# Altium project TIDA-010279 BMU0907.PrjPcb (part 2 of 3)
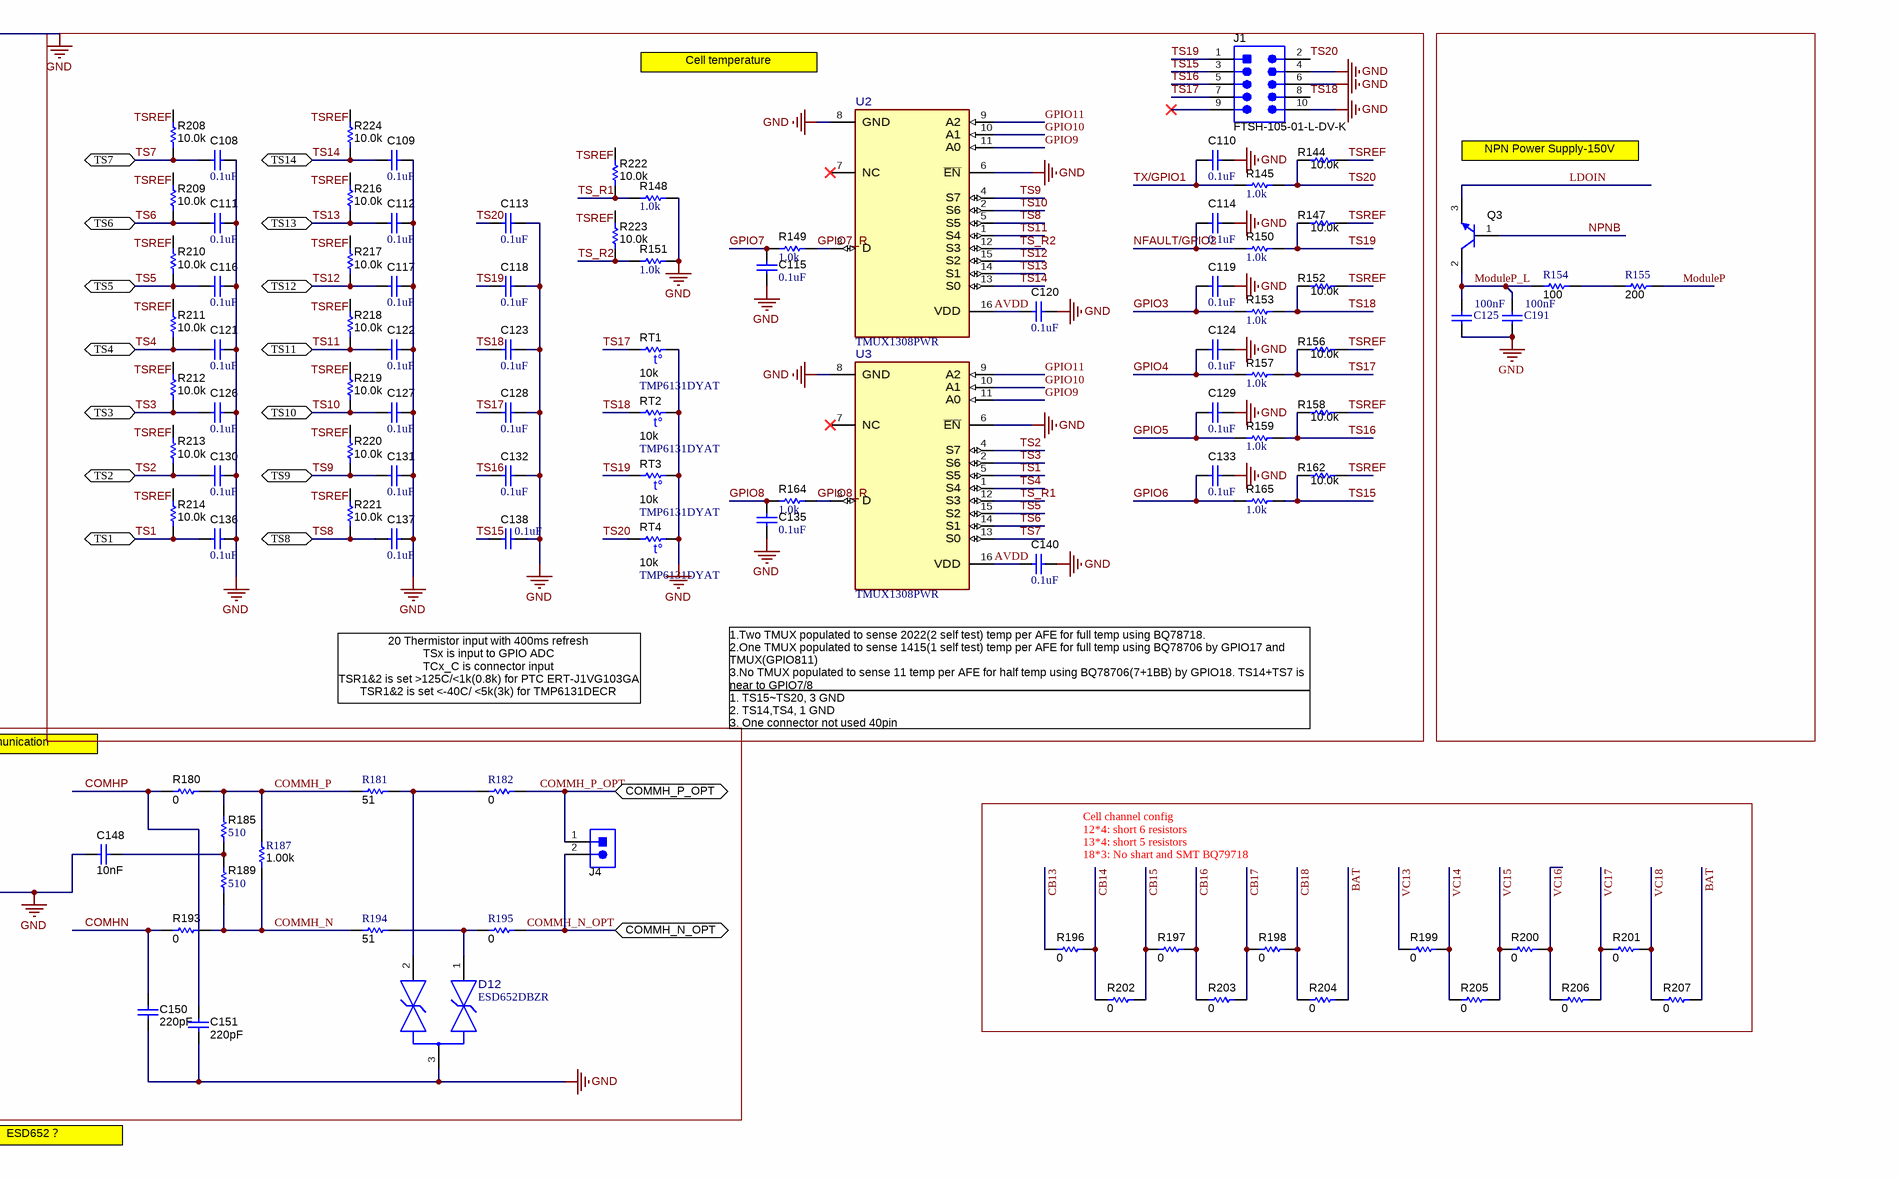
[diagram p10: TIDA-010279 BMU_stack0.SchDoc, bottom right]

## Sheet TIDA-010279 BMU_stack0.SchDoc (continued)

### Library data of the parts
C1-C4 C15-C17 C34-C36 C52-C54 C62 C68 C72-C74 C76 C80 C85 C90 C93-C95 C97 C103 C108-C124 C126-C133 C135-C138 C140 = CMP-0006356-2: CAP, CERM, 0.1 uF, 50 V, +/- 10%, X7R, AEC-Q200 Grade 1, 0402; Manufacturer: MuRata; TaMin_C: -55°C; Polarized: N; SizeAreaWB_mm2: 3; Value1: Unknown; U/M: EA; Value: 0.1uF; TaMax_C: 125°C; SizeZ_mm: 0.6; SizeX_mm: 1; SizeY_mm: 0.5; Value2: 50V; AEC Qualified: Y; Cap_F: 100nF; AEC Category: Q200
C5 C6 C8 C9 C11 C12 C19 C20 C23 C24 C27 C28 C31 C32 C39 C40 C42 C43 C47 C48 C50 C51 C56 C57 C59 C60 C65 C66 C69 C70 C77 C78 C82 C83 C86 C87 C91 C92 C99 C100 = CMP-0096840-1: Cap Ceramic 22nF 100V X7R 10% Pad SMD 0603 +125°C Automotive T/R; Manufacturer: TDK; AEC Grade: Grade 1; SizeZ_mm: 1.1mm; Tolerance_%: 0.1%; AEC Qualified: Yes; TempCo: 0.15
C7 C14 C22 C30 C37 C45 C49 C58 C61 C63 C67 C71 C75 C79 C81 C84 C88 C89 C96 C98 C101 C102 C104-C107 = CMP-0006361-2: CAP, CERM, 4700 pF, 50 V, +/- 10%, X7R, AEC-Q200 Grade 1, 0402; Manufacturer: MuRata; TaMin_C: -55°C; Polarized: N; SizeAreaWB_mm2: 3; Value1: Unknown; U/M: EA; Value: 4700pF; TaMax_C: 125°C; SizeZ_mm: 0.6; SizeX_mm: 1; SizeY_mm: 0.5; Value2: 50V; AEC Qualified: Y; Cap_F: 4.7nF; AEC Category: Q200
C18 = CMP-0080738-1: CAP, CERM, 4.7 µF, 10 V,+/- 5%, X7R, AEC-Q200 Grade 1, 0805; Manufacturer: Kemet; AEC Grade: 1; AEC Qualified: Y; SizeZ_mm: 1.45; VDC_V: 10V; SizeAreaWB_mm2: 6.75; SizeArea_mm2: 2.5; AEC Category: Q200; Value: 4.7uF; TaMax_C: 125°C; Polarized: N; TaMin_C: -55°C; SizeY_mm: 1.25; U/M: EA; SizeX_mm: 2; Cap_Case: 0805
C26 = CMP-0084773-1: CAP, CERM, 0.01 µF, 100 V,+/- 10%, X7R, AEC-Q200 Grade 1, 0603; Manufacturer: MuRata; SizeArea_mm2: 1.28; ValueDisplayed: 0.01µF; Polarized: N; AEC Grade: 1; Value2: 100V; SizeY_mm: 0.8; Cap_Case: 0603; TaMax_C: 125°C; Value: 0.01uF; SizeAreaWB_mm2: 4.68; TaMin_C: -55°C; CompType: Capacitor; AEC Category: Q200; U/M: EA; AEC Qualified: Y; SizeX_mm: 1.6
C38 C55 = CMP-0007136-5: CAP, CERM, 1 uF, 16 V, +/- 10%, X7R, AEC-Q200 Grade 1, 0603; Manufacturer: MuRata; TaMin_C: -55°C; Polarized: N; SizeAreaWB_mm2: 4.68; Value1: Unknown; U/M: EA; Value: 1uF; TaMax_C: 125°C; SizeZ_mm: 1; SizeX_mm: 1.6; SizeY_mm: 0.8; Value2: 16V; SizeArea_mm2: 1.28; AEC Qualified: Y; AEC Category: Q200
C46 C64 = CMP-0007138-4: CAP, CERM, 0.47 uF, 16 V, +/- 10%, X7R, AEC-Q200 Grade 1, 0603; Manufacturer: MuRata; Polarized: N; CompType: Capacitor; Value: 0.47uF; U/M: EA; Cap_F: 470nF; Value1: Unknown; VDC_V: 16V; TaMin_C: -55°C; TaMax_C: 125°C; AEC Category: Q200; AEC Qualified: Y; AEC Grade: 1; SizeAreaWB_mm2: 4.68; SizeX_mm: 1.6; SizeY_mm: 0.8; SizeArea_mm2: 1.28
C125 C191 = CMP-0119652-1: WCAP-CSGP Multilayer Ceramic Chip Capacitor, General Purpose, size 1206, X7R, 100nF, 100VDC; Manufacturer: Wurth Elektronik; Capacitance Tolerance: +/-10%; Case/Size Code: 1206; Dissipation Factor: 2.5%; Insulation Resistance: 1GOhm; Rated Voltage (DC): 100V; Technical Reference: X7R1206104K100DFCT10000
C147 C148 = CMP-0007143-4: CAP, CERM, 0.01 uF, 50 V, +/- 10%, X7R, AEC-Q200 Grade 1, 0603; Manufacturer: MuRata; TaMin_C: -55°C; Polarized: N; SizeAreaWB_mm2: 4.68; Value1: Unknown; U/M: EA; Value: 0.01uF; TaMax_C: 125°C; SizeZ_mm: 1; SizeX_mm: 1.6; SizeY_mm: 0.8; Value2: 50V; SizeArea_mm2: 1.28; AEC Qualified: Y; AEC Category: Q200
C149-C152 = CMP-0860329-1: CAP, CERM, 220 pF, 50 V,+/- 5%, X7R, 0603; Manufacturer: Samsung Electro-Mechanics; TaMin_C: -55°C; Polarized: N; SizeAreaWB_mm2: 4.68; U/M: EA; Value: 220pF; TaMax_C: 125°C; SizeZ_mm: 1; SizeX_mm: 1.6; SizeY_mm: 0.8; Value2: 50V; SizeArea_mm2: 1.28; CompType: Capacitor; AEC Category: Q200
D1 = CMP-0029023-2: Diode, Superfast Rectifier, 150 V, 1 A, SMA; Manufacturer: Diodes Inc.; TJmax_C: 150°C; Vr_V: 150V; Value2: 0.92V; SizeX_mm: 5.59; Green_REACh: Incomplete; SizeAreaWB_mm2: 37.3428; Value: 150V; Vf_V: 920mV; Green_Lifecycle: Not Set; Value1: 1A; SizeZ_mm: 2.87; SizeArea_mm2: 16.3228; SizeY_mm: 2.92; AEC Category: Q101; RJC_CperW: 25
D2 D3 = CMP-0002888-2: LED, Green, SMD; Manufacturer: Lite-On; Type: AlInGaP; Vf_V: 2V; Io_A: 20mA; Value1: W
D4 D5 = CMP-0033054-1: SMD16PL Series 60 V 1 A Surface Mount Schottky Rectifier - SOD-123FL; Manufacturer: Micro Commercial Co; AEC Qualified: No; SizeZ_mm: 1.35mm; TJmax_C: 125°C; Vf_V: 60V; Cap_F: 40pF; Forward Current: 1A; Max Surge Forward Current: 30A; Peak Reverse Current: 0.1mA
D6-D8 D10 = CMP-0005590-3: Diode, TVS, Uni, 85 V, 137 Vc, SMB; Manufacturer: Diodes Inc.; Vc: 137V; SizeX_mm: 5.6; SizeArea_mm2: 21.336; SizeAreaWB_mm2: 44.156; Ipp: 4.4A; SizeZ_mm: 2.6; Value1: 600W; Vbr_Min: 94.4V; AEC Category: Q101; SizeY_mm: 3.81; Vbr_Max: 108.2V
D9 = CMP-0084976-1: Diode, TVS, Uni, 85 V, 137 Vc, 400 W, 2.9 A, SMA; Manufacturer: Littelfuse; SizeX_mm: 5.59; Vbr_Min: 94.4V; Value1: 137V; AEC Category: Q101; SizeY_mm: 2.92; SizeZ_mm: 2.87; Ipp: 2.9A; RJA_CperW: 120; Vbr_Max: 104V; SizeAreaWB_mm2: 37.3428; AEC Qualified: N; SizeArea_mm2: 16.3228; Ppk: 400W
D11 D12 = CMP-0122986-1: 18V two-channel bidirectional ESD protection diode; Manufacturer: Texas Instruments; AEC Qualified: No; SizeZ_mm: 1.12mm; Ipp: 5.5A; Ppk: 176W; Breakdown Voltage: 19V; Cap_F: 4pF; Clamping Voltage: 25V; Number Of Channels: 2; Standoff Height: 0.01mm; TJmax_C: +150°C
J1 = CMP-0075634-2: Header(Shrouded), 1.27mm, 5x2, Gold, SMT; Manufacturer: Samtec; Pitch_mm: 1.27; Gender: Male; Cert_CSA: Y; Current_A: 3.3A; Row_Count: 2
J2 = CMP-0123118-1: 2.00mm Wafer, Right Angle Connector, 40pins, Key-A With CPA Feature; Manufacturer: BEIJIDA ELECTRONICS TECHNOLOGY; ContactFinish: Tin,Nickel; Current_A: 3A; Row_Count: 2; Voltage_V: 60V; AEC Qualified: No; Conn Gender: Male; DUT-Pitch_mm: 2mm; SizeZ_mm: 9.6mm
J3 J4 = CMP-0002337-1: Header, 100mil, 2x1, Tin, TH; Manufacturer: Sullins Connector Solutions; CNHeader: TRUE; Current_A: 3A; Green_Lifecycle: Not Set; Shrouded: N; Gender: Male; Green_REACh: Incomplete; Voltage_V: 1.8kV; Row_Count: 1; Pitch_mm: 2.54; CT: FALSE; Cert_UL: Y
Q1 Q2 = CMP-0086180-1: MOSFET, N-CH, 20 V, 0.2 A, AEC-Q101, SC-89; Alternate Manufacturer: None; Manufacturer: Rohm; AEC Category: Q101; Value: 20V; SizeY_mm: 1.6; Vgs_V: 8V; SizeArea_mm2: 2.56; SizeAreaWB_mm2: 6.76; Value2: ? nC; ChMode: Enhancement; ChType: N; Value1: ? ohm; SizeZ_mm: 0.8; AEC Qualified: Y; IdsMax_A: 200mA
Q3 = CMP-0000504-4: Transistor, NPN, 150 V, 1 A, AEC-Q101, DPAK; Manufacturer: Diodes Inc.; PartNumber: ZXTN4004KTC; CompType: BJT; IcRated_A: 1A; PNP: 0; SizeArea_mm2: 64.8114; TaMax_C: 150°C; Vceo_V: 150V; TaMin_C: -55°C; SizeX_mm: 9.91; SizeY_mm: 6.54; SizeZ_mm: 2.29; Value1: 1 A; AEC Category: Q101; Vcesat1_V: 250mV; NPN: 1; SizeAreaWB_mm2: 101.7114; AEC Qualified: Y; Value: 150 V
R1-R18 R20-R25 R27-R35 R38-R40 R42-R50 R52-R60 R62-R64 R66-R74 R76-R78 R80-R82 R84-R87 = CMP-0020585-3: RES, 68, 5%, 0.125 W, AEC-Q200 Grade 0, 0805; Manufacturer: RESI; Power_W: 125mW; TempCo: 200 ppm/C; Value_Code: 68R0; Value: 68; EIA_Code: E24; SizeX_mm: 2; SizeY_mm: 1.25; SizeZ_mm: 1.45; Value2: 0.125W; SizeArea_mm2: 2.5; AEC Qualified: Y; VDC_V: 150V; AEC Category: Q200; AEC Grade: 0
R19 R26 R37 R41 R51 R61 R65 R75 R83 R90 R100 R104 R114 R126 R128 R132 R135 R138 R139 = CMP-0026071-3: RES, 1.00 k, 1%, 0.063 W, AEC-Q200 Grade 0, 0402; Manufacturer: Vishay-Dale; Power_W: 63mW; TempCo: 100 ppm/C; Value_Code: 1k00; Value: 1.00k; EIA_Code: E96; Res_ohm: 1k; SizeX_mm: 1; SizeY_mm: 0.5; SizeZ_mm: 0.6; Value2: 0.063W; AEC Qualified: Y; VDC_V: 50V; AEC Category: Q200; AEC Grade: 0
R36 = CMP-0021368-3: RES, 60.4, 1%, 0.125 W, AEC-Q200 Grade 0, 0805; Manufacturer: Vishay-Dale; Power_W: 125mW; TempCo: 100 ppm/C; Value_Code: 60R4; Value: 60.4; EIA_Code: E96; SizeX_mm: 2; SizeY_mm: 1.25; SizeZ_mm: 1.45; Value2: 0.125W; SizeArea_mm2: 2.5; AEC Qualified: Y; VDC_V: 150V; AEC Category: Q200; AEC Grade: 0
R79 = CMP-0026436-2: RES, 511, 1%, 0.063 W, AEC-Q200 Grade 0, 0402; Manufacturer: Vishay-Dale; Power_W: 63mW; TempCo: 100 ppm/C; Value_Code: 511R; Value: 511; EIA_Code: E96; SizeX_mm: 1; SizeY_mm: 0.5; SizeZ_mm: 0.6; Value2: 0.063W; AEC Qualified: Y; VDC_V: 50V; AEC Category: Q200; AEC Grade: 0
R121 R122 = CMP-0026918-5: RES, 3.3 k, 5%, 0.063 W, AEC-Q200 Grade 0, 0402; Manufacturer: Vishay-Dale; Power_W: 63mW; TempCo: 200 ppm/C; Value_Code: 3k30; Value: 3.3k; EIA_Code: E24; SizeX_mm: 1; SizeY_mm: 0.5; SizeZ_mm: 0.6; Value2: 0.063W; AEC Qualified: Y; VDC_V: 50V; AEC Category: Q200; AEC Grade: 0
R136 R137 = CMP-0025702-4: RES, 10 M, 5%, 0.1 W, AEC-Q200 Grade 0, 0603; Manufacturer: Vishay-Dale; Power_W: 100mW; TempCo: 200 ppm/C; Value_Code: 10M0; Value: 10Meg; EIA_Code: E24; SizeX_mm: 1.6; SizeY_mm: 0.8; SizeZ_mm: 1; Value2: 0.1W; SizeArea_mm2: 1.28; AEC Qualified: Y; VDC_V: 75V; AEC Category: Q200; AEC Grade: 0
R140 R196-R207 = CMP-0026822-3: RES, 0, 5%, 0.063 W, AEC-Q200 Grade 0, 0402; Manufacturer: Vishay-Dale; Power_W: 63mW; TempCo: 200 ppm/C; Value_Code: 0000; Value: 0; EIA_Code: E24; SizeX_mm: 1; SizeY_mm: 0.5; SizeZ_mm: 0.6; Value2: 0.063W; AEC Qualified: Y; VDC_V: 50V; AEC Category: Q200
R144 R147 R152 R156 R158 R162 R208-R214 R216-R224 = CMP-0025958-3: RES, 10.0 k, 1%, 0.063 W, AEC-Q200 Grade 0, 0402; Manufacturer: Vishay-Dale; Power_W: 63mW; TempCo: 100 ppm/C; Value_Code: 10k0; Value: 10.0k; EIA_Code: E96; Res_ohm: 10k; SizeX_mm: 1; SizeY_mm: 0.5; SizeZ_mm: 0.6; Value2: 0.063W; AEC Qualified: Y; VDC_V: 50V; AEC Category: Q200; AEC Grade: 0
R145 R148-R151 R153 R157 R159 R164 R165 = CMP-0026852-3: RES, 1.0 k, 5%, 0.063 W, AEC-Q200 Grade 0, 0402; Manufacturer: Vishay-Dale; Power_W: 63mW; TempCo: 200 ppm/C; Value_Code: 1k00; Value: 1.0k; EIA_Code: E24; Res_ohm: 1k; SizeX_mm: 1; SizeY_mm: 0.5; SizeZ_mm: 0.6; Value2: 0.063W; AEC Qualified: Y; VDC_V: 50V; AEC Category: Q200; AEC Grade: 0
R154 = CMP-0016209-3: RES, 100, 1%, 0.75 W, AEC-Q200 Grade 0, 2010; Manufacturer: Vishay-Dale; Power_W: 750mW; TempCo: 100 ppm/C; Value_Code: 100R; Value: 100; EIA_Code: E96; SizeX_mm: 5; SizeY_mm: 2.5; SizeZ_mm: 1.66; Value2: 0.75W; SizeArea_mm2: 12.5; AEC Qualified: Y; VDC_V: 400V; AEC Category: Q200; AEC Grade: 0
R155 = CMP-0016302-3: RES, 200, 1%, 0.75 W, AEC-Q200 Grade 0, 2010; Manufacturer: Vishay-Dale; Power_W: 750mW; TempCo: 100 ppm/C; Value_Code: 200R; Value: 200; EIA_Code: E96; SizeX_mm: 5; SizeY_mm: 2.5; SizeZ_mm: 1.66; Value2: 0.75W; SizeArea_mm2: 12.5; AEC Qualified: Y; VDC_V: 400V; AEC Category: Q200; AEC Grade: 0
R177 R182 R190 R195 = CMP-0025885-5: RES, 0, 5%, 0.1 W, 0603; Manufacturer: Yageo; Power_W: 100mW; TempCo: 200 ppm/C; Value_Code: 0000; Value: 0; EIA_Code: E24; SizeX_mm: 1.6; SizeY_mm: 0.8; SizeZ_mm: 1; Value2: 0.1W; SizeArea_mm2: 1.28; AEC Qualified: N; VDC_V: 75V; AEC Category: Q200; SizeAreaWB_mm2: 4.68
R178 R181 R194 = CMP-0025825-4: RES, 51, 5%, 0.1 W, AEC-Q200 Grade 0, 0603; Manufacturer: Vishay-Dale; Power_W: 100mW; TempCo: 200 ppm/C; Value_Code: 51R0; Value: 51; EIA_Code: E24; SizeX_mm: 1.6; SizeY_mm: 0.8; SizeZ_mm: 1; Value2: 0.1W; SizeArea_mm2: 1.28; AEC Qualified: Y; VDC_V: 75V; AEC Category: Q200; AEC Grade: 0
R179 R180 R192 R193 = CMP-0025874-4: RES, 0, 5%, 0.1 W, AEC-Q200 Grade 0, 0603; Manufacturer: Panasonic; Power_W: 100mW; TempCo: 600 ppm/C; Value_Code: 0000; Value: 0; EIA_Code: E24; SizeX_mm: 1.6; SizeY_mm: 0.8; SizeZ_mm: 1; Value2: 0.1W; SizeArea_mm2: 1.28; AEC Qualified: Y; AEC Category: Q200; VDC_V: 50V; SizeAreaWB_mm2: 4.68
R184 R185 R188 R189 = CMP-0025823-4: RES, 510, 5%, 0.1 W, AEC-Q200 Grade 0, 0603; Manufacturer: Vishay-Dale; Power_W: 100mW; TempCo: 200 ppm/C; Value_Code: 510R; Value: 510; EIA_Code: E24; SizeX_mm: 1.6; SizeY_mm: 0.8; SizeZ_mm: 1; Value2: 0.1W; SizeArea_mm2: 1.28; AEC Qualified: Y; VDC_V: 75V; AEC Category: Q200; AEC Grade: 0
R186 R187 = CMP-0022680-4: RES, 1.00 k, 1%, 0.1 W, 0603; Manufacturer: Panasonic; Power_W: 100mW; TempCo: 100 ppm/C; Value_Code: 1k00; Value: 1.00k; EIA_Code: E96; Res_ohm: 1k; SizeX_mm: 1.6; SizeY_mm: 0.8; SizeZ_mm: 1; Value2: 0.1W; SizeArea_mm2: 1.28; VDC_V: 75V; AEC Category: Q200; U/M: EA
R191 = CMP-0025825-4: RES, 51, 5%, 0.1 W, AEC-Q200 Grade 0, 0603; Manufacturer: Vishay-Dale; TempCo: 200 ppm/C; Value: 51; SizeX_mm: 1.6; SizeY_mm: 0.8; SizeZ_mm: 1; Value2: 0.1W; SizeArea_mm2: 1.28; AEC Qualified: Y; VDC_V: 75V; AEC Category: Q200; AEC Grade: 0; Power_W: 100mW; Value_Code: 51R0; EIA_Code: E24
R215 R257 = CMP-0025950-3: RES, 100 k, 1%, 0.063 W, AEC-Q200 Grade 0, 0402; Manufacturer: Vishay-Dale; Power_W: 63mW; TempCo: 100 ppm/C; Value: 100k; EIA_Code: E96; SizeX_mm: 1; SizeY_mm: 0.5; SizeZ_mm: 0.6; Value2: 0.063W; AEC Qualified: Y; VDC_V: 50V; AEC Category: Q200; AEC Grade: 0
RT1-RT4 = CMP-0091865-2: ±1% tolerance 10kΩ linear thermistor available in 0402 and 0603 package options 2-SOT-5X3 -40 to 125; Manufacturer: Texas Instruments; Max Current: 400uA; AEC Qualified: No; TJmax_C: +155°C; TaMin_C: -40°C; TempCo: 6400ppm/°C; TaMax_C: +125°C; VDC_V: 5.5V; SizeZ_mm: 0.77mm; AEC Category: Q200; CompType: IC
U1 = CMP-0122614-1: Functional Safety-Compliant 14S Battery Monitor; Manufacturer: Texas Instruments; SizeZ_mm: 1.2mm; AEC Qualified: No; Max Supply Voltage: 70V; Min Supply Voltage: 9V; Nominal Supply Current: 3.5mA; Number Of Cells: 14; Standoff Height: 0.05mm; TaMax_C: +125°C; TaMin_C: -40°C; TJmax_C: +150°C
U2 U3 = CMP-0090991-1: 5-V, 8: 1, 1-channel general-purpose multiplexer with 1.8-V logic control 16-TSSOP -40 to 125; Manufacturer: Texas Instruments; Max Supply Voltage: 5.5V; AEC Qualified: No; PositionCount: 1; Min Supply Voltage: 1.62V; -3Db Bandwith: 350-500MHz; Mux Demux Ratio: 8:1; Nominal Supply Current: 1uA; SizeZ_mm: 1.2mm; TaMin_C: -40°C; TaMax_C: +125°C; Standoff Height: 0.05mm; TJmax_C: +150°C; On State Resistance: 75-650Ω

## Sheet TIDA-010279 BMU_CAN MCU.SchDoc
size 558 x 431 mm; Date: Not shown in title block; ApprovedBy: Not shown in title block; CheckedBy: Not shown in title block; Author: Not shown in title block; CompanyName: Not shown in title block; Engineer: Not shown in title block; Organization: Not shown in title block; Address1: Not shown in title block; Address2: Not shown in title block; Address3: Not shown in title block; Address4: Not shown in title block; DocumentNumber: 1; Revision: Use project parameter SCH_Rev; SheetNumber: 4; SheetTotal: 4; PageSetup: Record=PageOptions¦CenterHorizontal=True¦CenterVertical=True¦PrintScale=1.00¦XCorrection=1.00¦YCorrection=1.00¦PrintKind=0¦BorderSize=5000000¦LeftOffset=0¦BottomOffset=0¦Orientation=2¦PaperLength=1000¦PaperWidth=1000¦Scale=100¦PaperSource=15¦PrintQuality=600¦MediaType=1¦DitherType=10¦PaperKind=Letter¦PrintScaleMode=1
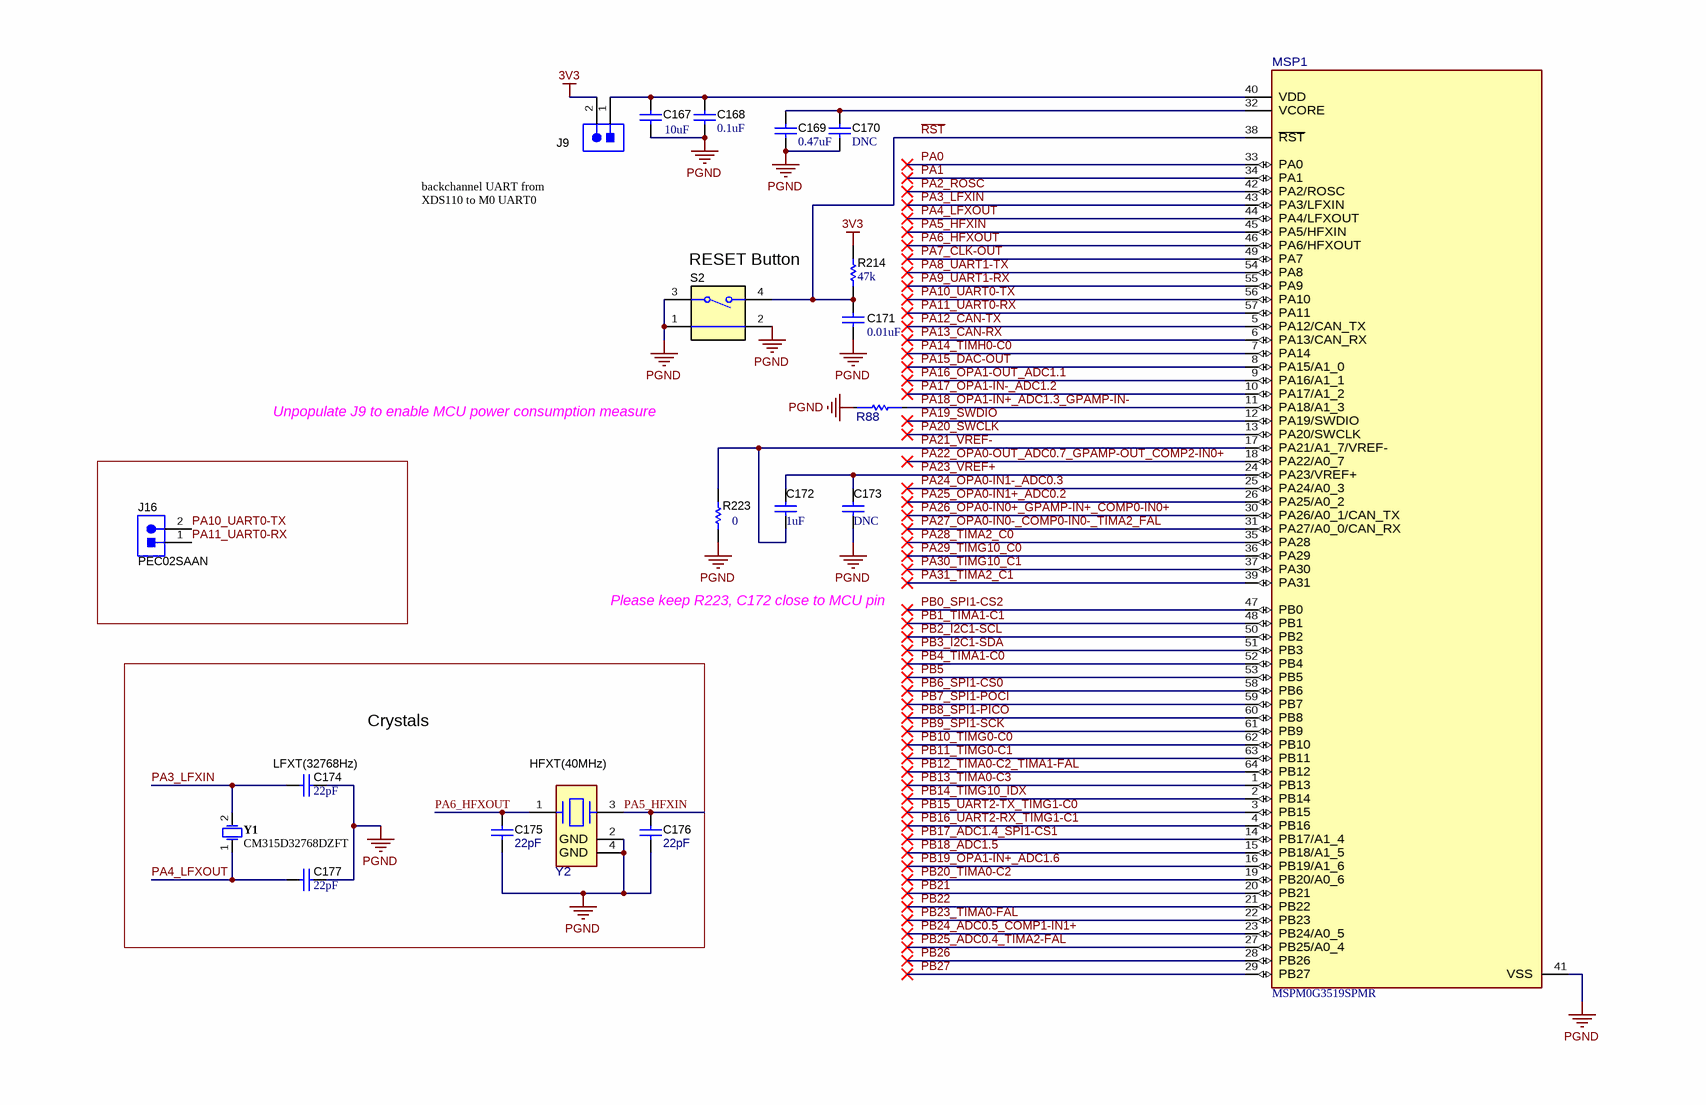
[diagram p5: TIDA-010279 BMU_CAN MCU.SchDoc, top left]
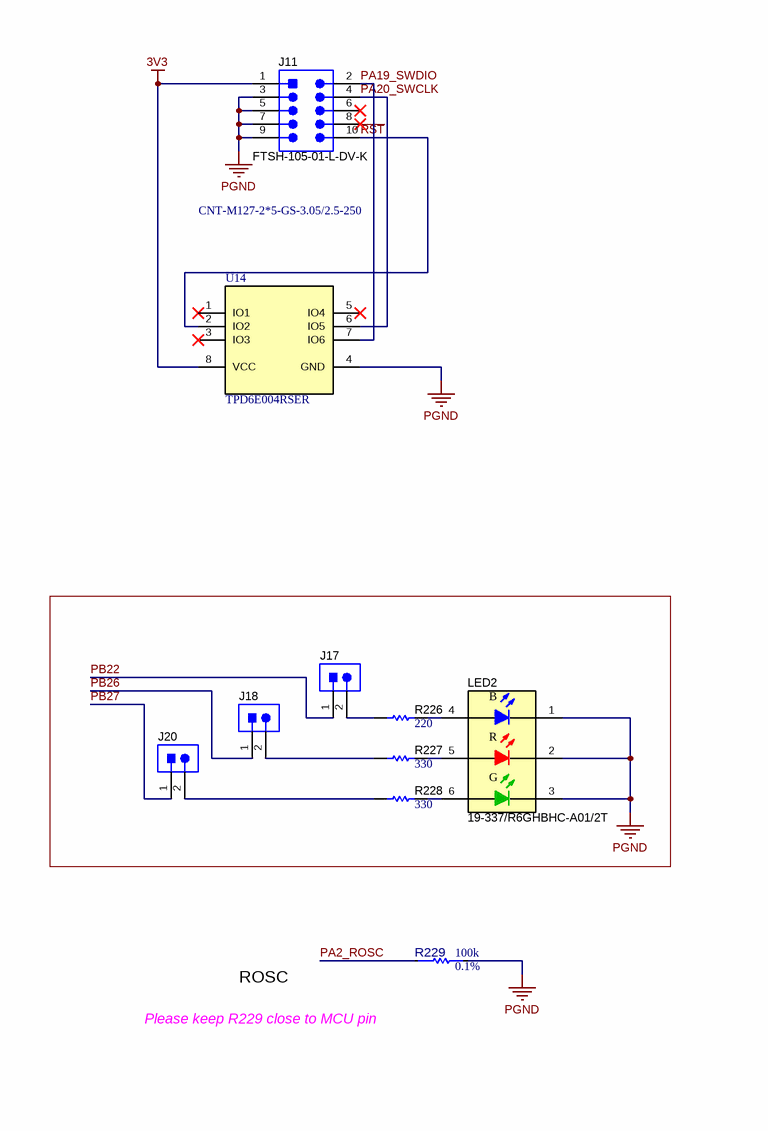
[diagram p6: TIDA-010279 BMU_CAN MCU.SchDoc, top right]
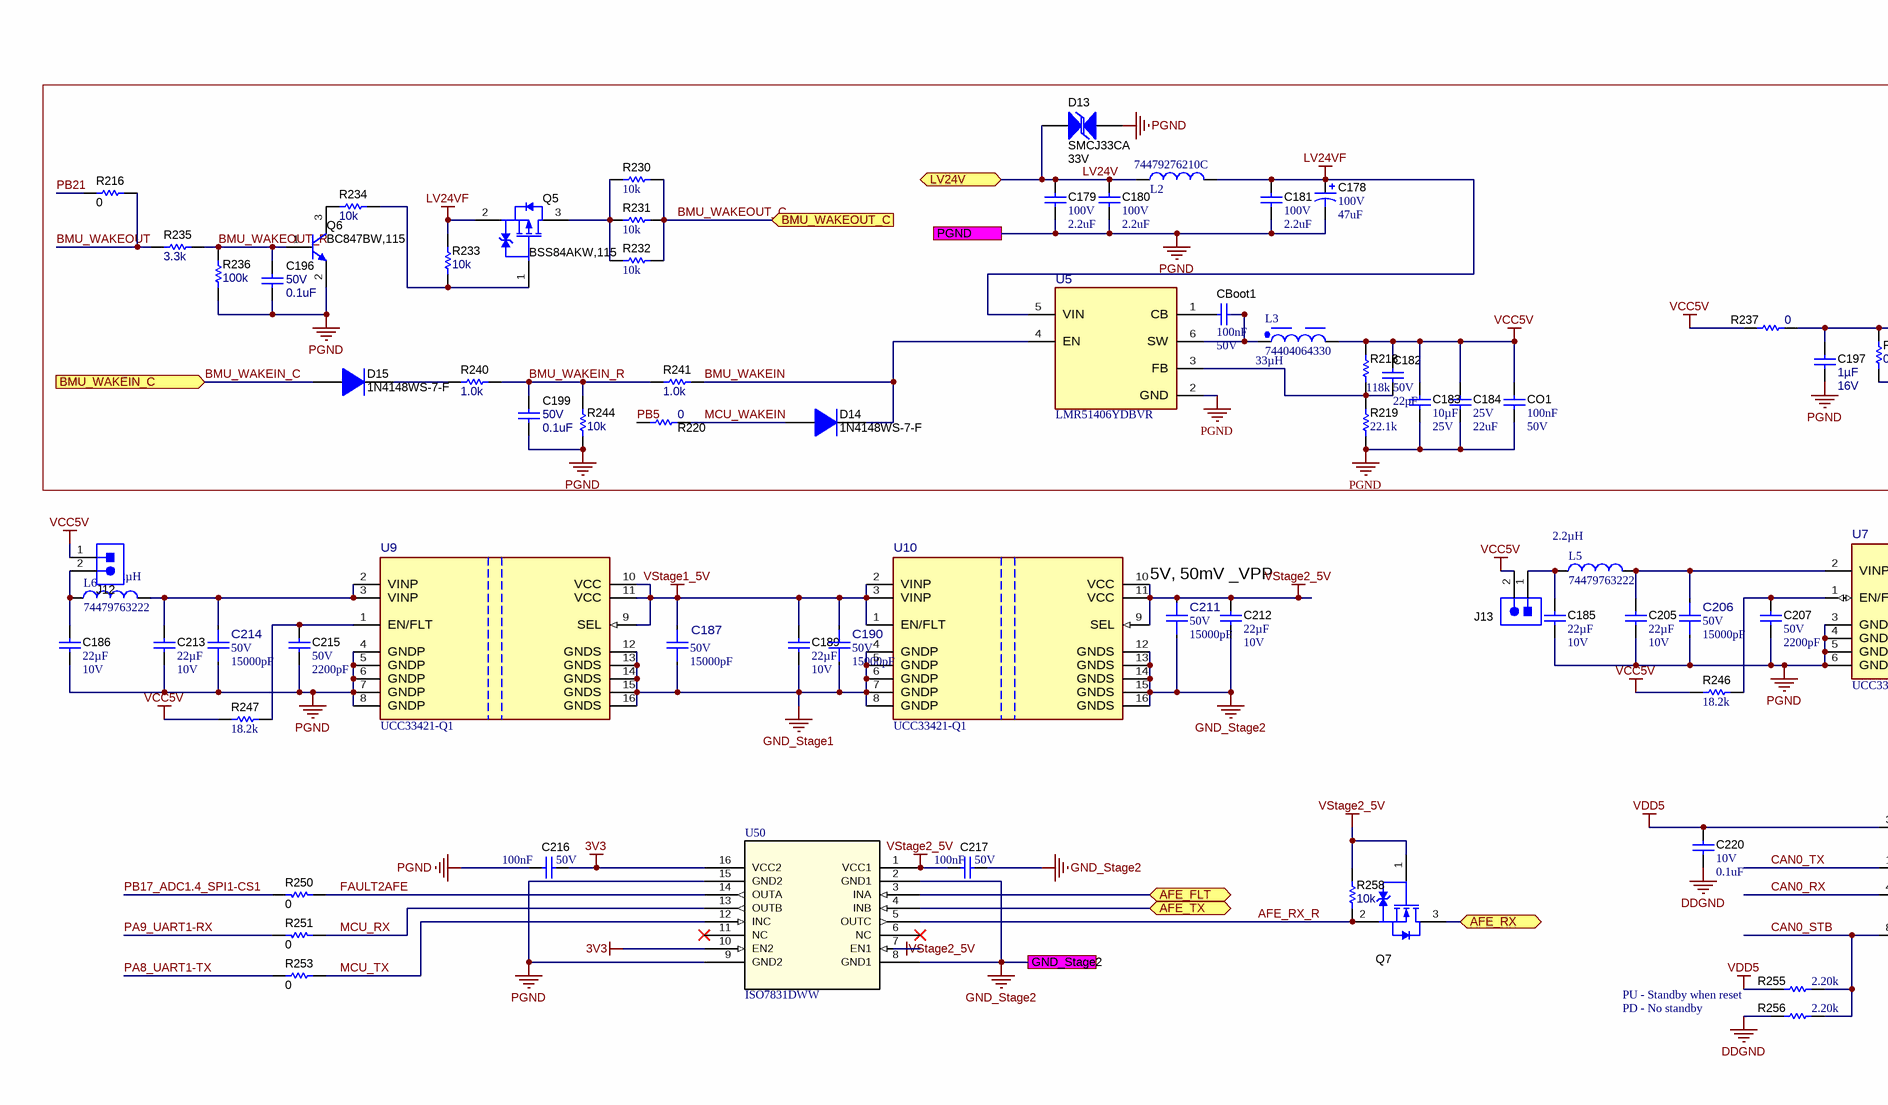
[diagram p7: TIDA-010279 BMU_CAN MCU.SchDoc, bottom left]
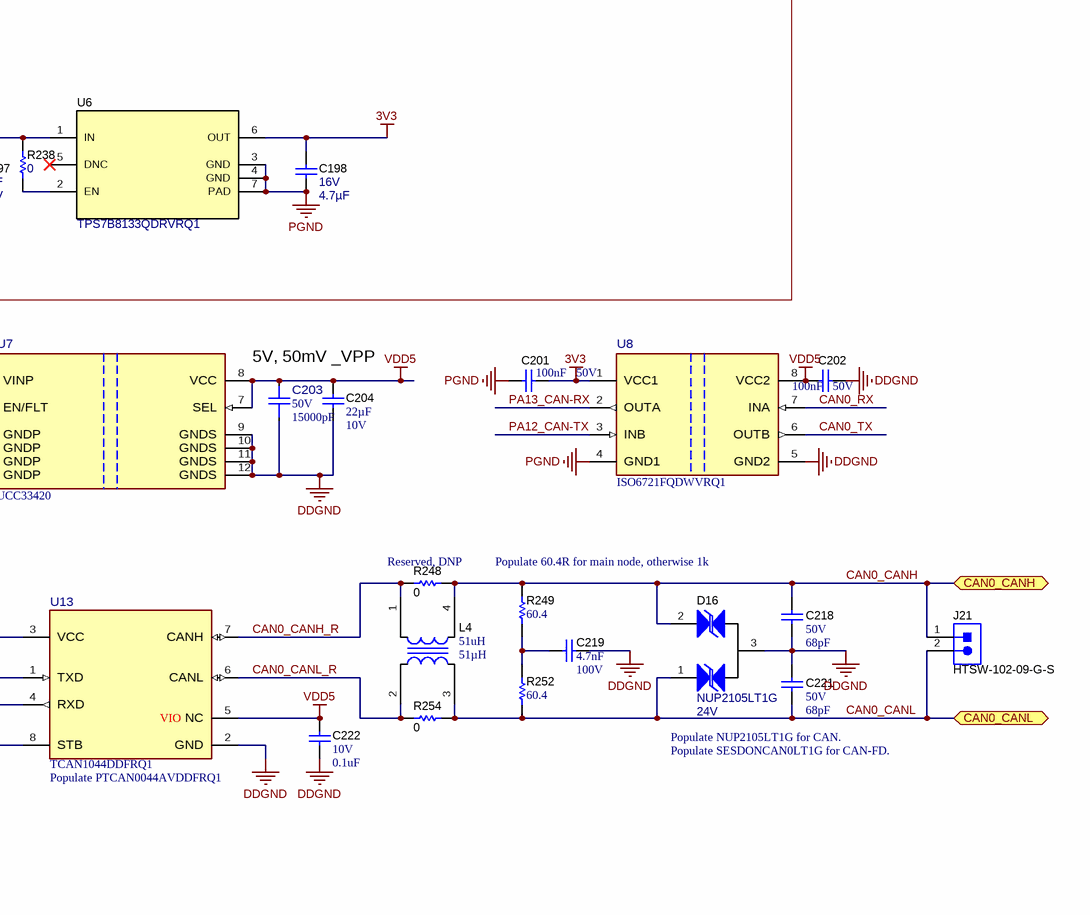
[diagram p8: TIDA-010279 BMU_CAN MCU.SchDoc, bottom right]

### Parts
C167  ValueDisplayed: 10uF  [0603]  (hidden comment: GRM188R60J106ME84)
C168  ValueDisplayed: 0.1uF  [0402]  (hidden comment: GRM155R61H104ME14D)
C169  ValueDisplayed: 0.47uF  [0402]  (hidden comment: GRM155R60J474KE19D)
C170  ValueDisplayed: DNC  [0402]  (hidden comment: GRM155R61H104ME14D)  (no BOM)
C171  ValueDisplayed: 0.01uF  [0402]  (hidden comment: GRM155R61C103KA01D)
C172  value 1uF  [0603]  (hidden comment: C1608X5R1E105K080AC)
C173  ValueDisplayed: DNC  [0603]  (hidden comment: C1608X5R1E105K080AC)  (no BOM)
C174  ValueDisplayed: 22pF  [0402]  (hidden comment: GRM1555C1H220JA01D)
C175  ValueDisplayed: 22pF  [0402]  (hidden comment: GRM1555C1H220JA01D)
C176  ValueDisplayed: 22pF  [0402]  (hidden comment: GRM1555C1H220JA01D)
C177  ValueDisplayed: 22pF  [0402]  (hidden comment: GRM1555C1H220JA01D)
C178  VDC_V: 100V  ValueDisplayed: 47uF  [Panasonic_H13]  (hidden comment: EEV-TG2A470Q)
C179  VDC_V: 100V  ValueDisplayed: 2.2uF  [1206_180]  (hidden comment: C3216X7S2A225K160AB)
C180  VDC_V: 100V  ValueDisplayed: 2.2uF  [1206_180]  (hidden comment: C3216X7S2A225K160AB)
C181  VDC_V: 100V  ValueDisplayed: 2.2uF  [1206_180]  (hidden comment: C3216X7S2A225K160AB)
C182  value 22pF  VDC_V: 50V  [0603]  (hidden comment: CGA3E2C0G1H220J080AA)
C183  Cap_F: 10µF  VDC_V: 25V  [0805_HV]  (hidden comment: GRM21BZ71E106KE15L)
C184  VDC_V: 25V  ValueDisplayed: 22uF  [1812_280]  (hidden comment: CGA8P1X7R1E226M250KC)
C185  Cap_F: 22µF  VDC_V: 10V  [0805_HV]  (hidden comment: GRM21BZ71A226ME15L)
C186  Cap_F: 22µF  VDC_V: 10V  [0805_HV]  (hidden comment: GRM21BZ71A226ME15L)
C187  VDC_V: 50V  ValueDisplayed: 15000pF  [FP-GCM155R71H153KA55D_0402-MFG]  (hidden comment: GCM155R71H153KA55D)
C189  Cap_F: 22µF  VDC_V: 10V  [0805_HV]  (hidden comment: GRM21BZ71A226ME15L)
C190  VDC_V: 50V  ValueDisplayed: 15000pF  [FP-GCM155R71H153KA55D_0402-MFG]  (hidden comment: GCM155R71H153KA55D)
C196  VDC_V: 50V  ValueDisplayed: 0.1uF  [0402]  (hidden comment: GCM155R71H104KE02D)
C197  Cap_F: 1µF  VDC_V: 16V  [0603]  (hidden comment: GCM188R71C105KA64D)
C198  VDC_V: 16V  ValueDisplayed: 4.7µF  [0603]  (hidden comment: GRT188R61C475KE13D)
C199  VDC_V: 50V  ValueDisplayed: 0.1uF  [0402]  (hidden comment: GCM155R71H104KE02D)
C201  Cap_F: 100nF  VDC_V: 50V  [0603]  (hidden comment: 06035C104KAT2A)
C202  Cap_F: 100nF  VDC_V: 50V  [0603]  (hidden comment: 06035C104KAT2A)
C203  VDC_V: 50V  ValueDisplayed: 15000pF  [FP-GCM155R71H153KA55D_0402-MFG]  (hidden comment: GCM155R71H153KA55D)
C204  Cap_F: 22µF  VDC_V: 10V  [0805_HV]  (hidden comment: GRM21BZ71A226ME15L)
C205  Cap_F: 22µF  VDC_V: 10V  [0805_HV]  (hidden comment: GRM21BZ71A226ME15L)
C206  VDC_V: 50V  ValueDisplayed: 15000pF  [FP-GCM155R71H153KA55D_0402-MFG]  (hidden comment: GCM155R71H153KA55D)
C207  VDC_V: 50V  ValueDisplayed: 2200pF  [0402]  (hidden comment: GCM155R71H222KA37D)
C211  VDC_V: 50V  ValueDisplayed: 15000pF  [FP-GCM155R71H153KA55D_0402-MFG]  (hidden comment: GCM155R71H153KA55D)
C212  Cap_F: 22µF  VDC_V: 10V  [0805_HV]  (hidden comment: GRM21BZ71A226ME15L)
C213  Cap_F: 22µF  VDC_V: 10V  [0805_HV]  (hidden comment: GRM21BZ71A226ME15L)
C214  VDC_V: 50V  ValueDisplayed: 15000pF  [FP-GCM155R71H153KA55D_0402-MFG]  (hidden comment: GCM155R71H153KA55D)
C215  VDC_V: 50V  ValueDisplayed: 2200pF  [0402]  (hidden comment: GCM155R71H222KA37D)
C216  Cap_F: 100nF  VDC_V: 50V  [0603]  (hidden comment: 06035C104KAT2A)
C217  Cap_F: 100nF  VDC_V: 50V  [0603]  (hidden comment: 06035C104KAT2A)
C218  VDC_V: 50V  ValueDisplayed: 68pF  [0603]  (hidden comment: GCM1885C1H680JA16D)
C219  Cap_F: 4.7nF  VDC_V: 100V  [0603]  (hidden comment: GCM188R72A472KA37D)
C220  VDC_V: 10V  ValueDisplayed: 0.1uF  [0402]  (hidden comment: GCM155R71A104KA55D)
C221  VDC_V: 50V  ValueDisplayed: 68pF  [0603]  (hidden comment: GCM1885C1H680JA16D)
C222  VDC_V: 10V  ValueDisplayed: 0.1uF  [0402]  (hidden comment: GCM155R71A104KA55D)
CBoot1  Cap_F: 100nF  VDC_V: 50V  [0603]  (hidden comment: 06035C104KAT2A)
CO1  Cap_F: 100nF  VDC_V: 50V  [0805_HV]  (hidden comment: 08055C104JAT2A)
D13  SMCJ33CA  value 33V  [SMC_Bi]
D14  1N4148WS-7-F  [SOD-323]
D15  1N4148WS-7-F  [SOD-323]
D16  NUP2105LT1G  value 24V  [SOT-23]
J9  90120-0122  [CONN_90120-0122]  (value not drawn)
J11  FTSH-105-01-L-DV-K  [Samtec_FTSH-105-01-x-DV-K]
J12  90120-0122  [CONN_90120-0122]  (value not drawn)
J13  90120-0122  [CONN_90120-0122]  (value not drawn)
J16  PEC02SAAN  [CONN_PEC02SAAN]
J17  90120-0122  [CONN_90120-0122]  (value not drawn)
J18  90120-0122  [CONN_90120-0122]  (value not drawn)
J20  90120-0122  [CONN_90120-0122]  (value not drawn)
J21  HTSW-102-09-G-S  [Samtec_HTSW-102-09-x-S]
L2  74479276210C  [WE-PMCI_0806_L2W1.6H1]
L3  74404064330  Inductance: 33µH  [WE-LQS_6045]
L4  value 51uH  ValueDisplayed: 51µH  [ACT45B_NoSilk]  (hidden comment: ACT45B-510-2P-TL003)
L5  74479763222  Inductance: 2.2µH  [WE-PMI_0603_L1.6W0.8H0.8]
L6  74479763222  Inductance: 2.2µH  [WE-PMI_0603_L1.6W0.8H0.8]
LED2  19-337/R6GHBHC-A01/2T  [19-337_RGB]
MSP1  PartNumber: MSPM0G3519SPMR  [PM0064A-MFG]  (hidden comment: MSPM0G3507SPM)
Q5  BSS84AKW,115  [SOT-323]
Q6  BC847BW,115  [SOT-323]
Q7  RE1C002UNTCL  [SC-89]  (value not drawn)
R88  ERJ-2GEJ473X  [FP-ERJ-2GEJ473X_0402-MFG]  (value not drawn)
R214  ValueDisplayed: 47k  [0402]  (hidden comment: CRCW040247K0JNED)
R216  ValueDisplayed: 0  [0402]  (hidden comment: CRCW04020000Z0ED)
R218  ValueDisplayed: 118k  [0402]  (hidden comment: CRCW0402118KFKED)
R219  ValueDisplayed: 22.1k  [0402]  (hidden comment: CRCW040222K1FKED)
R220  ValueDisplayed: 0  [0603]  (hidden comment: CRCW06030000Z0EA)
R223  value 0  [0603]  (hidden comment: RC0603JR-070RL)
R226  ValueDisplayed: 220  [0402]  (hidden comment: CRCW0402220RJNED)
R227  ValueDisplayed: 330  [0402]  (hidden comment: CRCW0402330RJNED)
R228  ValueDisplayed: 330  [0402]  (hidden comment: CRCW0402330RJNED)
R229  Tolerance_%: 0.1%  Res_ohm: 100k  [FP-ERA-2AEB104X_0402-MFG]  (hidden comment: ERA-2AEB104X)
R230  ValueDisplayed: 10k  [0603]  (hidden comment: CRCW060310K0JNEA)
R231  ValueDisplayed: 10k  [0603]  (hidden comment: CRCW060310K0JNEA)
R232  ValueDisplayed: 10k  [0603]  (hidden comment: CRCW060310K0JNEA)
R233  ValueDisplayed: 10k  [0402]  (hidden comment: CRCW040210K0JNED)
R234  ValueDisplayed: 10k  [0402]  (hidden comment: CRCW040210K0JNED)
R235  ValueDisplayed: 3.3k  [0402]  (hidden comment: CRCW04023K30JNED)
R236  ValueDisplayed: 100k  [0402]  (hidden comment: CRCW0402100KJNED)
R237  ValueDisplayed: 0  [0603]  (hidden comment: CRCW06030000Z0EA)
R238  ValueDisplayed: 0  [0603]  (hidden comment: CRCW06030000Z0EA)
R240  ValueDisplayed: 1.0k  [0402]  (hidden comment: CRCW04021K00JNED)
R241  ValueDisplayed: 1.0k  [0402]  (hidden comment: CRCW04021K00JNED)
R244  ValueDisplayed: 10k  [0402]  (hidden comment: CRCW040210K0JNED)
R246  ValueDisplayed: 18.2k  [0603]  (hidden comment: CRCW060318K2FKEA)
R247  ValueDisplayed: 18.2k  [0603]  (hidden comment: CRCW060318K2FKEA)
R248  ValueDisplayed: 0  [0402]  (hidden comment: CRCW04020000Z0ED)
R249  ValueDisplayed: 60.4  [1206]  (hidden comment: ERJ-8ENF60R4V)
R250  ValueDisplayed: 0  [0402]  (hidden comment: CRCW04020000Z0ED)
R251  ValueDisplayed: 0  [0402]  (hidden comment: CRCW04020000Z0ED)
R252  ValueDisplayed: 60.4  [1206]  (hidden comment: ERJ-8ENF60R4V)
R253  ValueDisplayed: 0  [0402]  (hidden comment: CRCW04020000Z0ED)
R254  ValueDisplayed: 0  [0402]  (hidden comment: CRCW04020000Z0ED)
R255  ValueDisplayed: 2.20k  [0402]  (hidden comment: ERJ-2RKF2201X)
R256  ValueDisplayed: 2.20k  [0402]  (hidden comment: ERJ-2RKF2201X)
R258  ValueDisplayed: 10k  [0402]  (hidden comment: CRCW040210K0JNED)
S2  1188E-1K2-V-TR  [SW_1188E]  (value not drawn)
U5  PartNumber: LMR51406YDBVR  [DBV0006A-MFG]  (hidden comment: LMR51410YDBVR)
U6  TPS7B8133QDRVRQ1  [DRV0006A]
U7  UCC33420  [RAQ0012B-MFG]
U8  ISO6721FQDWVRQ1  [DWV0008A-MFG]
U9  UCC33421-Q1  [DWX0016A-MFG]
U10  UCC33421-Q1  [DWX0016A-MFG]
U13  TCAN1044DDFRQ1  [DDF0008A-MFG]
U14  TPD6E004RSER  [RSE0008A]
U50  ISO7831DWW  [SOIC16_DWW_TEX]
Y1  CM315D32768DZFT  [CMHT-CM315D-2_V]
Y2  X1E0000210179  [FP-X1E0000210179_TSX-3225-MFG]  (value not drawn)

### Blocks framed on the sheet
Crystals: C174-C177 Y1 Y2

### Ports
AFE_FLT (bidir), AFE_RX (bidir), AFE_TX (bidir), BMU_WAKEIN_C (in), BMU_WAKEOUT_C (in), CAN0_CANH (bidir), CAN0_CANL (bidir), GND_Stage2, LV24V (bidir), PGND

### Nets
3V3: C198.1 C201.2 C216.1 J9.2 J11.1 R214.2 U6.6(OUT) U8.1(VCC1) U14.8(VCC) U50.10(EN2) U50.16(VCC2)
DDGND: C202.2 C203.1 C204.2 C218.2 C219.2 C220.1 C221.1 C222.2 D16.3 R256.2 U7.9(GNDS) U7.10(GNDS) U7.11(GNDS) U7.12(GNDS) U8.5(GND2) U13.2(GND)
GND_Stage1: C187.1 C189.2 C190.1 U9.12(GNDS) U9.13(GNDS) U9.14(GNDS) U9.15(GNDS) U9.16(GNDS) U10.4(GNDP) U10.5(GNDP) U10.6(GNDP) U10.7(GNDP) U10.8(GNDP)
GND_Stage2: C211.1 C212.2 C217.1 U10.12(GNDS) U10.13(GNDS) U10.14(GNDS) U10.15(GNDS) U10.16(GNDS) U50.2(GND1) U50.8(GND1) ; port GND_Stage2
LV24VF: C178.1(+) C181.1 L2.2 Q5.2(S) R233.2 U5.5(VIN)
PGND: C167.2 C168.2 C169.2 C170.2 C171.2 C173.2 C174.1 C175.1 C176.1 C177.1 C178.2(-) C179.2 C180.2 C181.2 C183.2 C184.2 C185.2 C186.2 C196.2 C197.2 C198.2 C199.2 C201.1 C205.2 C206.1 C207.2 C213.2 C214.1 C215.2 C216.2 CO1.2 D13.1 J11.3 J11.5 J11.7 J11.9 LED2.1(K) LED2.2(K) LED2.3(K) MSP1.41(VSS) Q6.2(E) R88.1 R219.1 R223.1 R229.2 R236.1 R244.1 S2.1 S2.2 S2.3 U5.2(GND) U6.3(GND) U6.4(GND) U6.7(PAD) U7.3(GNDP) U7.4(GNDP) U7.5(GNDP) U7.6(GNDP) U8.4(GND1) U9.4(GNDP) U9.5(GNDP) U9.6(GNDP) U9.7(GNDP) U9.8(GNDP) U14.4(GND) U50.9(GND2) U50.15(GND2) Y2.2(GND) Y2.4(GND) ; port PGND
VCC5V: C182.1 C183.1 C184.1 CO1.1 J12.1 J13.2 L3.2 R218.2 R237.1 R246.1 R247.1
VDD5: C202.1 C203.2 C204.1 C220.2 C222.1 R255.2 U7.7(SEL) U7.8(VCC) U8.8(VCC2) U13.3(VCC) U13.5(NC)
VStage1_5V: C187.2 C189.1 C190.2 U9.9(SEL) U9.10(VCC) U9.11(VCC) U10.1(EN/FLT) U10.2(VINP) U10.3(VINP)
VStage2_5V: C211.2 C212.1 C217.2 Q7.1(G) R258.2 U10.9(SEL) U10.10(VCC) U10.11(VCC) U50.1(VCC1) U50.7(EN1)
AFE_FLT: U50.3(INA) ; port AFE_FLT
AFE_RX: Q7.3(D) ; port AFE_RX
AFE_RX_R: Q7.2(S) R258.1 U50.5(OUTC)
AFE_TX: U50.4(INB) ; port AFE_TX
BMU_WAKEIN: D14.1(K) R241.2 U5.4(EN)
BMU_WAKEIN_C: D15.2(A) ; port BMU_WAKEIN_C
BMU_WAKEIN_R: C199.1 R240.2 R241.1 R244.2
BMU_WAKEOUT: R216.2 R235.1
BMU_WAKEOUT_C: R230.2 R231.2 R232.2 ; port BMU_WAKEOUT_C
BMU_WAKEOUT_R: C196.1 Q6.1(B) R235.2 R236.2
CAN0_CANH: C218.1 D16.2 J21.1 L4.4 R248.2 R249.2 ; port CAN0_CANH
CAN0_CANH_R: L4.1 R248.1 U13.7(CANH)
CAN0_CANL: C221.2 D16.1 J21.2 L4.3 R252.1 R254.2 ; port CAN0_CANL
CAN0_CANL_R: L4.2 R254.1 U13.6(CANL)
CAN0_RX: U8.7(INA) U13.4(RXD)
CAN0_STB: R255.1 R256.1 U13.8(STB)
CAN0_TX: U8.6(OUTB) U13.1(TXD)
FAULT2AFE: R250.1 U50.14(OUTA)
LV24V: C179.1 C180.1 D13.2 L2.1 ; port LV24V
MCU_RX: R251.1 U50.13(OUTB)
MCU_TX: R253.2 U50.12(INC)
MCU_WAKEIN: D14.2(A) R220.2
PA0: MSP1.33(PA0)
PA1: MSP1.34(PA1)
PA2_ROSC: MSP1.42(PA2/ROSC) R229.1
PA3_LFXIN: C174.2 MSP1.43(PA3/LFXIN) Y1.2
PA4_LFXOUT: C177.2 MSP1.44(PA4/LFXOUT) Y1.1
PA5_HFXIN: C176.2 MSP1.45(PA5/HFXIN) Y2.3
PA6_HFXOUT: C175.2 MSP1.46(PA6/HFXOUT) Y2.1
PA7_CLK-OUT: MSP1.49(PA7)
PA8_UART1-TX: MSP1.54(PA8) R253.1
PA9_UART1-RX: MSP1.55(PA9) R251.2
PA10_UART0-TX: J16.2 MSP1.56(PA10)
PA11_UART0-RX: J16.1 MSP1.57(PA11)
PA12_CAN-TX: MSP1.5(PA12/CAN_TX) U8.3(INB)
PA13_CAN-RX: MSP1.6(PA13/CAN_RX) U8.2(OUTA)
PA14_TIMH0-C0: MSP1.7(PA14)
PA15_DAC-OUT: MSP1.8(PA15/A1_0)
PA16_OPA1-OUT_ADC1.1: MSP1.9(PA16/A1_1)
PA17_OPA1-IN-_ADC1.2: MSP1.10(PA17/A1_2)
PA18_OPA1-IN+_ADC1.3_GPAMP-IN-: MSP1.11(PA18/A1_3) R88.2
PA19_SWDIO: J11.2 MSP1.12(PA19/SWDIO) U14.7(IO6)
PA20_SWCLK: J11.4 MSP1.13(PA20/SWCLK) U14.6(IO5)
PA21_VREF-: C172.2 MSP1.17(PA21/A1_7/VREF-) R223.2
PA22_OPA0-OUT_ADC0.7_GPAMP-OUT_COMP2-IN0+: MSP1.18(PA22/A0_7)
PA23_VREF+: C172.1 C173.1 MSP1.24(PA23/VREF+)
PA24_OPA0-IN1-_ADC0.3: MSP1.25(PA24/A0_3)
PA25_OPA0-IN1+_ADC0.2: MSP1.26(PA25/A0_2)
PA26_OPA0-IN0+_GPAMP-IN+_COMP0-IN0+: MSP1.30(PA26/A0_1/CAN_TX)
PA27_OPA0-IN0-_COMP0-IN0-_TIMA2_FAL: MSP1.31(PA27/A0_0/CAN_RX)
PA28_TIMA2_C0: MSP1.35(PA28)
PA29_TIMG10_C0: MSP1.36(PA29)
PA30_TIMG10_C1: MSP1.37(PA30)
PA31_TIMA2_C1: MSP1.39(PA31)
PB0_SPI1-CS2: MSP1.47(PB0)
PB1_TIMA1-C1: MSP1.48(PB1)
PB2_I2C1-SCL: MSP1.50(PB2)
PB3_I2C1-SDA: MSP1.51(PB3)
PB4_TIMA1-C0: MSP1.52(PB4)
PB5: MSP1.53(PB5) R220.1
PB6_SPI1-CS0: MSP1.58(PB6)
PB7_SPI1-POCI: MSP1.59(PB7)
PB8_SPI1-PICO: MSP1.60(PB8)
PB9_SPI1-SCK: MSP1.61(PB9)
PB10_TIMG0-C0: MSP1.62(PB10)
PB11_TIMG0-C1: MSP1.63(PB11)
PB12_TIMA0-C2_TIMA1-FAL: MSP1.64(PB12)
PB13_TIMA0-C3: MSP1.1(PB13)
PB14_TIMG10_IDX: MSP1.2(PB14)
PB15_UART2-TX_TIMG1-C0: MSP1.3(PB15)
PB16_UART2-RX_TIMG1-C1: MSP1.4(PB16)
PB17_ADC1.4_SPI1-CS1: MSP1.14(PB17/A1_4) R250.2
PB18_ADC1.5: MSP1.15(PB18/A1_5)
PB19_OPA1-IN+_ADC1.6: MSP1.16(PB19/A1_6)
PB20_TIMA0-C2: MSP1.19(PB20/A0_6)
PB21: MSP1.20(PB21) R216.1
PB22: J17.1 MSP1.21(PB22)
PB23_TIMA0-FAL: MSP1.22(PB23)
PB24_ADC0.5_COMP1-IN1+: MSP1.23(PB24/A0_5)
PB25_ADC0.4_TIMA2-FAL: MSP1.27(PB25/A0_4)
PB26: J18.1 MSP1.28(PB26)
PB27: J20.1 MSP1.29(PB27)
~{RST}: C171.1 J11.10 MSP1.38(~{RST}) R214.1 S2.4 U14.2(IO2)
NetC167_1: C167.1 C168.1 J9.1 MSP1.40(VDD)
NetC169_1: C169.1 C170.1 MSP1.32(VCORE)
NetC182_2: C182.2 R218.1 R219.2 U5.3(FB)
NetC185_1: C185.1 J13.1 L5.1
NetC186_1: C186.1 J12.2 L6.1
NetC197_1: C197.1 R237.2 R238.2 U6.1(IN)
NetC205_1: C205.1 C206.2 L5.2 U7.2(VINP)
NetC207_1: C207.1 R246.2 U7.1(EN/FLT)
NetC213_1: C213.1 C214.2 L6.2 U9.2(VINP) U9.3(VINP)
NetC215_1: C215.1 R247.2 U9.1(EN/FLT)
NetC219_1: C219.1 R249.1 R252.2
NetCBoot1_1: CBoot1.1 U5.1(CB)
NetCBoot1_2: CBoot1.2 L3.1 U5.6(SW)
NetD15_1: D15.1(K) R240.1
NetJ17_2: J17.2 R226.1
NetJ18_2: J18.2 R227.1
NetJ20_2: J20.2 R228.1
NetLED2_4: LED2.4(A) R226.2
NetLED2_5: LED2.5(A) R227.2
NetLED2_6: LED2.6(A) R228.2
NetQ5_1: Q5.1(G) R233.1 R234.1
NetQ5_3: Q5.3(D) R230.1 R231.1 R232.1
NetQ6_3: Q6.3(C) R234.2
NetR238_1: R238.1 U6.2(EN)

Not connected (* = marked no-connect by the designer): J11 6* 8*; U6 5(DNC)*; U14 1(IO1)* 3(IO3)* 5(IO4)*; U50 6(NC)* 11(NC)*

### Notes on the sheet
- CNT-M127-2*5-GS-3.05/2.5-250
- backchannel UART from XDS110 to M0 UART0
- (near S2) RESET Button
- Unpopulate J9 to enable MCU power consumption measure
- Please keep R223, C172 close to MCU pin
- (near C174) LFXT(32768Hz)
- HFXT(40MHz)
- Please keep R229 close to MCU pin
- ROSC
- 5V, 50mV _VPP
- (near R248) Reserved, DNP
- (near R249) Populate 60.4R for main node, otherwise 1k
- (near U13) VIO
- (near U13) Populate PTCAN0044AVDDFRQ1
- Populate NUP2105LT1G for CAN.
- Populate SESDONCAN0LT1G for CAN-FD.
- PU - Standby when reset
- PD - No standby

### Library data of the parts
C167 = CMP-0007304-5: CAP, CERM, 10 uF, 6.3 V, +/- 20%, X5R, 0603; Manufacturer: MuRata; TaMin_C: -55°C; Polarized: N; SizeAreaWB_mm2: 4.68; Value1: Unknown; U/M: EA; Value: 10uF; TaMax_C: 85°C; SizeZ_mm: 1; SizeX_mm: 1.6; SizeY_mm: 0.8; Value2: 6.3V; SizeArea_mm2: 1.28; Cap_F: 10µF; AEC Category: Q200
C168 C170 = CMP-0006614-2: CAP, CERM, 0.1 uF, 50 V, +/- 20%, X5R, 0402; Manufacturer: MuRata; TaMin_C: -55°C; Polarized: N; SizeAreaWB_mm2: 3; Value1: Unknown; U/M: EA; Value: 0.1uF; TaMax_C: 85°C; SizeZ_mm: 0.6; SizeX_mm: 1; SizeY_mm: 0.5; Value2: 50V; Cap_F: 100nF; AEC Category: Q200
C169 = CMP-0006551-2: CAP, CERM, 0.47 uF, 6.3 V, +/- 10%, X5R, 0402; Manufacturer: MuRata; TaMin_C: -55°C; Polarized: N; SizeAreaWB_mm2: 3; Value1: Unknown; U/M: EA; Value: 0.47uF; TaMax_C: 85°C; SizeZ_mm: 0.6; SizeX_mm: 1; SizeY_mm: 0.5; Value2: 6.3V; Cap_F: 470nF; AEC Category: Q200
C171 = CMP-0006590-2: CAP, CERM, 0.01 uF, 16 V, +/- 10%, X5R, 0402; Manufacturer: MuRata; TaMin_C: -55°C; Polarized: N; SizeAreaWB_mm2: 3; Value1: Unknown; U/M: EA; Value: 0.01uF; TaMax_C: 85°C; SizeZ_mm: 0.6; SizeX_mm: 1; SizeY_mm: 0.5; Value2: 16V; Cap_F: 10nF; AEC Category: Q200
C172 = CMP-0007006-5: CAP, CERM, 1 uF, 25 V, +/- 10%, X5R, 0603; Manufacturer: TDK; TaMin_C: -55°C; Polarized: N; SizeAreaWB_mm2: 4.68; Value1: Unknown; U/M: EA; TaMax_C: 85°C; SizeZ_mm: 1; SizeX_mm: 1.6; SizeY_mm: 0.8; Value2: 25V; SizeArea_mm2: 1.28; Cap_F: 1µF; AEC Category: Q200; ValueDisplayed: DNC
C173 = CMP-0007006-5: CAP, CERM, 1 uF, 25 V, +/- 10%, X5R, 0603; Manufacturer: TDK; TaMin_C: -55°C; Polarized: N; SizeAreaWB_mm2: 4.68; Value1: Unknown; U/M: EA; Value: 1uF; TaMax_C: 85°C; SizeZ_mm: 1; SizeX_mm: 1.6; SizeY_mm: 0.8; Value2: 25V; SizeArea_mm2: 1.28; Cap_F: 1µF; AEC Category: Q200
C174-C177 = CMP-0006439-2: CAP, CERM, 22 pF, 50 V, +/- 5%, C0G/NP0, 0402; Manufacturer: MuRata; TaMin_C: -55°C; Polarized: N; SizeAreaWB_mm2: 3; Value1: Unknown; U/M: EA; Value: 22pF; TaMax_C: 125°C; SizeZ_mm: 0.6; SizeX_mm: 1; SizeY_mm: 0.5; Value2: 50V; AEC Category: Q200
C178 = CMP-0011227-2: CAP, AL, 47 uF, 100 V, +/- 20%, 0.42 ohm, AEC-Q200 Grade 1, SMD; Manufacturer: Panasonic; TaMin_C: -40°C; ESR_ohm: 4.2d; Polarized: Y; SizeAreaWB_mm2: 240.25; U/M: EA; Value: 47uF; TaMax_C: 125°C; SizeZ_mm: 14; SizeX_mm: 13.5; Cap_Case: 12.5x13.5mm; SizeArea_mm2: 182.25; CompType: Capacitor; Cap_F: 47µF; IRMS_A: 2.5dA; AEC Grade: 1; AEC Category: Q200
C179-C181 = CMP-0008724-2: CAP, CERM, 2.2 uF, 100 V, +/- 10%, X7S, 1206; Manufacturer: TDK; TaMin_C: -55°C; ESR_ohm: 5.718m; Polarized: N; SizeAreaWB_mm2: 10.92; Value1: 0.005718 ohm; U/M: EA; Value: 2.2uF; TaMax_C: 125°C; SizeZ_mm: 1.8; SizeX_mm: 3.2; SizeY_mm: 1.6; SizeArea_mm2: 5.12; Cap_F: 2.2µF; IRMS_A: 3.03632A; AEC Category: Q200
C182 = CMP-0007071-4: CAP, CERM, 22 pF, 50 V, +/- 5%, C0G/NP0, AEC-Q200 Grade 1, 0603; Manufacturer: TDK; TaMin_C: -55°C; Polarized: N; SizeAreaWB_mm2: 4.68; Value1: Unknown; U/M: EA; TaMax_C: 125°C; SizeZ_mm: 1; SizeX_mm: 1.6; SizeY_mm: 0.8; SizeArea_mm2: 1.28; AEC Qualified: Y; AEC Category: Q200
C183 = CMP-0008378-2: CAP, CERM, 10 uF, 25 V, +/- 10%, X7R, 0805; Manufacturer: MuRata; TaMin_C: -55°C; Polarized: N; SizeAreaWB_mm2: 6.75; Value1: Unknown; U/M: EA; Value: 10uF; TaMax_C: 125°C; SizeZ_mm: 1.45; SizeX_mm: 2; SizeY_mm: 1.25; Cap_Case: 0805; SizeArea_mm2: 2.5; AEC Category: Q200
C184 = CMP-0009402-2: CAP, CERM, 22 uF, 25 V, +/- 20%, X7R, AEC-Q200 Grade 1,; Manufacturer: TDK; TaMin_C: -55°C; ESR_ohm: 2.434m; Polarized: N; SizeAreaWB_mm2: 23.1; Value1: 0.002434 ohm; U/M: EA; Value: 22uF; TaMax_C: 125°C; SizeZ_mm: 2.8; SizeX_mm: 4.5; SizeY_mm: 3.2; SizeArea_mm2: 14.4; AEC Qualified: Y; Cap_F: 22µF; IRMS_A: 4.91649A; AEC Grade: 1; AEC Category: Q200
C185 C186 C189 C204 C205 C212 C213 = CMP-0008377-2: CAP, CERM, 22 uF, 10 V, +/- 20%, X7R, 0805; Manufacturer: MuRata; SizeY_mm: 1.25; Cap_Case: 0805; SizeArea_mm2: 2.5; AEC Qualified: N; AEC Category: Q200; ValueDisplayed: 22uF; TaMin_C: -55°C; SizeAreaWB_mm2: 6.75; Value1: Unknown; U/M: EA; Value: 22uF; TaMax_C: 125°C; SizeZ_mm: 1.45; SizeX_mm: 2
C187 C190 C203 C206 C211 C214 = CMP-0090630-1: 0.015µF ±10% 50V Ceramic Capacitor X7R 0402 (1005 Metric); Manufacturer: Murata; SizeZ_mm: 0.55mm; AEC Qualified: Yes; AEC Grade: Grade 1; Value: 15nF; TempCo: 15%
C196 C199 = CMP-0006356-2: CAP, CERM, 0.1 uF, 50 V, +/- 10%, X7R, AEC-Q200 Grade 1, 0402; Manufacturer: MuRata; TaMin_C: -55°C; Polarized: N; SizeAreaWB_mm2: 3; Value1: Unknown; U/M: EA; Value: 0.1uF; TaMax_C: 125°C; SizeZ_mm: 0.6; SizeX_mm: 1; SizeY_mm: 0.5; AEC Qualified: Y; Cap_F: 100nF; AEC Category: Q200
C197 = CMP-0007136-5: CAP, CERM, 1 uF, 16 V, +/- 10%, X7R, AEC-Q200 Grade 1, 0603; Manufacturer: MuRata; TaMin_C: -55°C; Polarized: N; SizeAreaWB_mm2: 4.68; Value1: Unknown; U/M: EA; Value: 1uF; TaMax_C: 125°C; SizeZ_mm: 1; SizeX_mm: 1.6; SizeY_mm: 0.8; SizeArea_mm2: 1.28; AEC Qualified: Y; AEC Category: Q200
C198 = CMP-0081052-1: CAP, CERM, 4.7 µF, 16 V,+/- 10%, X5R, AEC-Q200 Grade 3, 0603; Manufacturer: MuRata; SizeAreaWB_mm2: 4.68; SizeArea_mm2: 1.28; AEC Qualified: Y; AEC Category: Q200; Value: 4.7uF; TaMax_C: 85°C; SizeZ_mm: 1; AEC Grade: 3; Polarized: N; TaMin_C: -55°C; SizeY_mm: 0.8; U/M: EA; SizeX_mm: 1.6
C201 C202 C216 C217 CBoot1 = CMP-0006802-4: CAP, CERM, 0.1 uF, 50 V, +/- 10%, X7R, 0603; Manufacturer: AVX; TaMin_C: -55°C; Polarized: N; SizeAreaWB_mm2: 4.68; Value1: Unknown; U/M: EA; Value: 0.1uF; TaMax_C: 125°C; SizeZ_mm: 1; SizeX_mm: 1.6; SizeY_mm: 0.8; SizeArea_mm2: 1.28; AEC Category: Q200
C207 C215 = CMP-0006357-2: CAP, CERM, 2200 pF, 50 V, +/- 10%, X7R, AEC-Q200 Grade 1, 0402; Manufacturer: MuRata; TaMin_C: -55°C; Polarized: N; SizeAreaWB_mm2: 3; Value1: Unknown; U/M: EA; Value: 2200pF; TaMax_C: 125°C; SizeZ_mm: 0.6; SizeX_mm: 1; SizeY_mm: 0.5; AEC Qualified: Y; Cap_F: 2.2nF; AEC Category: Q200
C218 C221 = CMP-0007129-4: CAP, CERM, 68 pF, 50 V, +/- 5%, C0G/NP0, AEC-Q200 Grade 1, 0603; Manufacturer: MuRata; TaMin_C: -55°C; Polarized: N; SizeAreaWB_mm2: 4.68; Value1: Unknown; U/M: EA; Value: 68pF; TaMax_C: 125°C; SizeZ_mm: 1; SizeX_mm: 1.6; SizeY_mm: 0.8; SizeArea_mm2: 1.28; AEC Qualified: Y; AEC Category: Q200
C219 = CMP-0079247-1: CAP, CERM, 4700 pF, 100 V,+/- 10%, X7R, AEC-Q200 Grade 1, 0603; Manufacturer: MuRata; SizeAreaWB_mm2: 4.68; SizeArea_mm2: 1.28; AEC Qualified: Y; AEC Category: Q200; Value: 4700pF; TaMax_C: 125°C; SizeZ_mm: 1; Polarized: N; TaMin_C: -55°C; SizeY_mm: 0.8; U/M: EA; SizeX_mm: 1.6
C220 C222 = CMP-0006350-2: CAP, CERM, 0.1 uF, 10 V, +/- 10%, X7R, AEC-Q200 Grade 1, 0402; Manufacturer: MuRata; TaMin_C: -55°C; Polarized: N; SizeAreaWB_mm2: 3; Value1: Unknown; U/M: EA; Value: 0.1uF; TaMax_C: 125°C; SizeZ_mm: 0.6; SizeX_mm: 1; SizeY_mm: 0.5; AEC Qualified: Y; Cap_F: 100nF; AEC Category: Q200
CO1 = CMP-0007631-2: CAP, CERM, 0.1 uF, 50 V, +/- 5%, X7R, 0805; Manufacturer: AVX; TaMin_C: -55°C; ESR_ohm: 0.024; Polarized: N; SizeAreaWB_mm2: 6.75; Value1: 0.024 ohm; U/M: EA; Value: 0.1uF; TaMax_C: 125°C; SizeZ_mm: 1.45; SizeX_mm: 2; SizeY_mm: 1.25; Cap_Case: 0805; SizeArea_mm2: 2.5; AEC Category: Q200
D13 = CMP-0005695-3: Diode, TVS, Bi, 33 V, SMC; Manufacturer: Littelfuse; SizeZ_mm: 2.6; Ppk: 1.5kW; Value1: 1500W; AEC Category: Q101; SizeArea_mm2: 50.5686; SizeX_mm: 8.13; SizeAreaWB_mm2: 83.2686; SizeY_mm: 6.22
D14 D15 = CMP-0079597-2: Diode, Switching, 75 V, 0.15 A, AEC-Q101, SOD-323; Manufacturer: Diodes Inc.; SizeX_mm: 2.7; Vf_V: 1.25V; AEC Qualified: Y; SizeArea_mm2: 3.645; AEC Category: Q101; SizeAreaWB_mm2: 8.695; Io_A: 150mA; SizeZ_mm: 1; Value1: 0.15A; SizeY_mm: 1.35; TJmax_C: 150°C; Vr_V: 75V; Value: 75V
D16 = CMP-0005919-3: Diode, TVS, Bi, 24 V, SOT-23; Manufacturer: ON Semiconductor; Value1: 350W; SizeAreaWB_mm2: 14; SizeY_mm: 3; SizeZ_mm: 1.1; SizeX_mm: 2.5; AEC Category: Q101; SizeArea_mm2: 7.5
J9 J12 J13 J17 J18 J20 = CMP-0055312-1: Header, 100mil, 2x1, Tin, TH; Manufacturer: Molex; CNHeader: TRUE; Green_Lifecycle: Active; Green_REACh: Passed; CT: FALSE
J11 = CMP-0075634-2: as J1 on sheet TIDA-010279 BMU_stack0
J16 = CMP-0002337-1: as J3 on sheet TIDA-010279 BMU_stack0
J21 = CMP-0075626-1: Header, 100mil, 2x1, Gold, TH; Manufacturer: Samtec; Pitch_mm: 2.54; Gender: Male; Cert_CSA: Y; CT: False; Row_Count: 1
L2 = CMP-0100947-1: WE-PMCI SMT Power Molded Chip Inductor, size 0806, 1uH, 4.4A, 60mOhm; Manufacturer: Wurth Elektronik; Case/Size Code: 0806; DC Resistance: 55mOhm; Saturation Current: 4.25A; Self Resonant Frequency: 95MHz; Type: Low RDC
L3 = CMP-1354-00075-2: NexarPartId: 46948302; Manufacturer: Wurth Elektronik; Tolerance: 20%; Test Frequency: 100kHz; Saturation Current: 1.8A; DC Resistance (DCR): 137mΩ; Max DC Current: 1.45A; Self Resonant Frequency: 12MHz; Series Resistance: 178.1mΩ; Shielding: Shielded; Core Material: Ferrite
L4 = CMP-0076845-1: Coupled inductor, 51 µH, 0.2 A, 1 ohm, AEC-Q200 Grade 0, SMD; Manufacturer: TDK; SizeAreaWB_mm2: 23.1; SizeArea_mm2: 14.4; AEC Qualified: Y; AEC Category: Q200; SizeZ_mm: 3.0; Green_REACh: Passed; AEC Grade: 0; SizeY_mm: 3.2; Green_Lifecycle: Active; DCR_ohm: 1; SizeX_mm: 4.5
L5 L6 = CMP-1392-00025-2: NexarPartId: 38797936; Manufacturer: Wurth Elektronik; DC Resistance (DCR): 300mΩ; Current Rating: 550mA
LED2 = CMP-0074720-2: LED, RGB, TH; Manufacturer: Everlight; Io_A: 25mA; Vr_V: 5V; Tjmax_C: 85°C; Angle: 120.0; Ir_A: 50µA; Vf_V: 3.8V
MSP1 = CMP-0093960-1: Mixed-Signal Microcontrollers With CAN-FD Interface LQFP64; Manufacturer: Texas Instruments; Number Of I2C Channels: 2; Frequency_Fixed: 80MHz; Number Of Cores: 1; Number Of Pwm Channels: 14; Data Bus Width: 32bits; Standoff Height: 0.05mm; SizeZ_mm: 1.6mm; Number Of I/Os: 60; Memory Type: FLASH; Min Supply Voltage: 1.62V; Number Of Adc Channels: 16; Memory Size: 128KBytes; TJmax_C: +130°C; Number Of Uart Channels: 4; Number Of Timers/Counters: 7; Max Supply Voltage: 3.6V; TaMin_C: -40°C; Core Architecture: ARM Cortex-M0+; Interface: I2C,SPI,UART,CAN,LIN,IrDA,SMBus; Ram Size: 32KBytes; AEC Qualified: No; TaMax_C: +125°C
Q5 = CMP-0000013-4: MOSFET, P-CH, -50 V, -0.15 A, AEC-Q101, SOT-323; Manufacturer: Nexperia; Alternate Manufacturer: None; AEC Category: Q101; SizeY_mm: 2.2; Value: -50V; ChMode: Enhancement; ChType: P; QgTyp_nC: 0.26; IdsMax_A: -150mA; Value2: 0.26 nC; SizeZ_mm: 1.1; SizeAreaWB_mm2: 10.24; AEC Qualified: Y; Vgs_V: -20V; SizeArea_mm2: 4.84
Q6 = CMP-0000486-2: Transistor, NPN, 45 V, 0.1 A, AEC-Q101, SOT-323; Manufacturer: NXP Semiconductor; TaMax_C: 150°C; Value2: 800; Value1: 0.1 A; Vcesat1_V: 90mV; SizeX_mm: 2.2; TaMin_C: -65°C; IcRated_A: 1dA; CompType: BJT; SizeZ_mm: 1.1; AEC Qualified: Y; Value: 45 V; SizeArea_mm2: 4.84; NPN: 1; Vceo_V: 45V; PNP: 0; AEC Category: Q101; SizeAreaWB_mm2: 10.24; U/M: EA
Q7 = CMP-0086180-1: as Q1 on sheet TIDA-010279 BMU_stack0
R88 = CMP-0122885-1: 47 kOhms ±5% 0.1W, 1/10W Chip Resistor 0402 (1005 Metric) Automotive AEC-Q200 Thick Film; Manufacturer: Panasonic; AEC Grade: Grade 0; AEC Qualified: Yes; Power_W: 100mW; Res_ohm: 47k; SizeZ_mm: 0.4mm; TempCo: 200ppm/°C; VDC_V: 50V; Value: 47k
R214 = CMP-0026935-3: RES, 47 k, 5%, 0.063 W, AEC-Q200 Grade 0, 0402; Manufacturer: Vishay-Dale; Power_W: 63mW; TempCo: 200 ppm/C; Value_Code: 47k0; Value: 47k; EIA_Code: E24; SizeX_mm: 1; SizeY_mm: 0.5; SizeZ_mm: 0.6; Value2: 0.063W; AEC Qualified: Y; VDC_V: 50V; AEC Category: Q200; AEC Grade: 0
R216 R248 R250 R251 R253 R254 = CMP-0026822-3: as R140 on sheet TIDA-010279 BMU_stack0
R218 = CMP-0025973-3: RES, 118 k, 1%, 0.063 W, AEC-Q200 Grade 0, 0402; Manufacturer: Vishay-Dale; Power_W: 63mW; TempCo: 100 ppm/C; Value: 118k; EIA_Code: E96; SizeX_mm: 1; SizeY_mm: 0.5; SizeZ_mm: 0.6; Value2: 0.063W; AEC Qualified: Y; VDC_V: 50V; AEC Category: Q200; AEC Grade: 0
R219 = CMP-0026178-2: RES, 22.1 k, 1%, 0.063 W, AEC-Q200 Grade 0, 0402; Manufacturer: Vishay-Dale; Power_W: 63mW; TempCo: 100 ppm/C; Value_Code: 22k1; Value: 22.1k; EIA_Code: E96; SizeX_mm: 1; SizeY_mm: 0.5; SizeZ_mm: 0.6; Value2: 0.063W; AEC Qualified: Y; VDC_V: 50V; AEC Category: Q200; AEC Grade: 0
R220 R237 R238 = CMP-0025697-4: RES, 0, 5%, 0.1 W, AEC-Q200 Grade 0, 0603; Manufacturer: Vishay-Dale; Power_W: 100mW; TempCo: 200 ppm/C; Value_Code: 0000; Value: 0; EIA_Code: E24; SizeX_mm: 1.6; SizeY_mm: 0.8; SizeZ_mm: 1; Value2: 0.1W; SizeArea_mm2: 1.28; AEC Qualified: Y; VDC_V: 75V; AEC Category: Q200
R223 = CMP-0025885-5: RES, 0, 5%, 0.1 W, 0603; Manufacturer: Yageo; Power_W: 100mW; TempCo: 200 ppm/C; Value_Code: 0000; EIA_Code: E24; SizeX_mm: 1.6; SizeZ_mm: 1; Value2: 0.1W; SizeArea_mm2: 1.28; AEC Qualified: N; VDC_V: 75V; AEC Category: Q200; ValueDisplayed: DNC; SizeY_mm: 0.8; SizeAreaWB_mm2: 4.68
R226 = CMP-0026878-3: RES, 220, 5%, 0.063 W, AEC-Q200 Grade 0, 0402; Manufacturer: Vishay-Dale; Power_W: 63mW; TempCo: 200 ppm/C; Value_Code: 220R; Value: 220; EIA_Code: E24; SizeX_mm: 1; SizeY_mm: 0.5; SizeZ_mm: 0.6; Value2: 0.063W; AEC Qualified: Y; VDC_V: 50V; AEC Category: Q200; AEC Grade: 0
R227 R228 = CMP-0026906-3: RES, 330, 5%, 0.063 W, AEC-Q200 Grade 0, 0402; Manufacturer: Vishay-Dale; Power_W: 63mW; TempCo: 200 ppm/C; Value_Code: 330R; Value: 330; EIA_Code: E24; SizeX_mm: 1; SizeY_mm: 0.5; SizeZ_mm: 0.6; Value2: 0.063W; AEC Qualified: Y; VDC_V: 50V; AEC Category: Q200; AEC Grade: 0
R229 = CMP-0088648-1: Res Thin Film 0402 100K Ohm 0.1% 1/16W ±25ppm/°C Molded SMD SMD Punched Carrier T/R; Manufacturer: Panasonic; Category 7542B8484461Ae85: Passive Components; VDC_V: 50V; Category Cd01000Bfc2916C6: Single Components; Power_W: 63mW; Category 5A00970A6D5C81C7: Uncategorized; AEC Qualified: Yes; SizeZ_mm: 0.4mm; Voltage: 25V; AEC Grade: Grade 0; Category 5C6A91606D4187Ad: Resistors
R230-R232 = CMP-0025701-4: RES, 10 k, 5%, 0.1 W, AEC-Q200 Grade 0, 0603; Manufacturer: Vishay-Dale; Power_W: 100mW; TempCo: 200 ppm/C; Value_Code: 10k0; Value: 10k; EIA_Code: E24; SizeX_mm: 1.6; SizeY_mm: 0.8; SizeZ_mm: 1; Value2: 0.1W; SizeArea_mm2: 1.28; AEC Qualified: Y; VDC_V: 75V; AEC Category: Q200; AEC Grade: 0
R233 R234 R244 R258 = CMP-0026825-5: RES, 10 k, 5%, 0.063 W, AEC-Q200 Grade 0, 0402; Manufacturer: Vishay-Dale; Power_W: 63mW; TempCo: 200 ppm/C; Value_Code: 10k0; Value: 10k; EIA_Code: E24; SizeX_mm: 1; SizeY_mm: 0.5; SizeZ_mm: 0.6; Value2: 0.063W; AEC Qualified: Y; VDC_V: 50V; AEC Category: Q200; AEC Grade: 0
R235 = CMP-0026918-5: as R121 on sheet TIDA-010279 BMU_stack0
R236 = CMP-0026823-3: RES, 100 k, 5%, 0.063 W, AEC-Q200 Grade 0, 0402; Manufacturer: Vishay-Dale; Power_W: 63mW; TempCo: 200 ppm/C; Value: 100k; EIA_Code: E24; SizeX_mm: 1; SizeY_mm: 0.5; SizeZ_mm: 0.6; Value2: 0.063W; AEC Qualified: Y; VDC_V: 50V; AEC Category: Q200; AEC Grade: 0
R240 R241 = CMP-0026852-3: as R145 on sheet TIDA-010279 BMU_stack0
R246 R247 = CMP-0022097-4: RES, 18.2 k, 1%, 0.1 W, AEC-Q200 Grade 0, 0603; Manufacturer: Vishay-Dale; Power_W: 100mW; TempCo: 100 ppm/C; Value_Code: 18k2; Value: 18.2k; EIA_Code: E96; SizeX_mm: 1.6; SizeY_mm: 0.8; SizeZ_mm: 1; Value2: 0.1W; SizeArea_mm2: 1.28; AEC Qualified: Y; VDC_V: 75V; AEC Category: Q200; AEC Grade: 0
R249 R252 = CMP-0017672-3: RES, 60.4, 1%, 0.25 W, AEC-Q200 Grade 0, 1206; Manufacturer: Panasonic; Power_W: 250mW; TempCo: 100 ppm/C; Value_Code: 60R4; Value: 60.4; EIA_Code: E96; SizeX_mm: 3.2; SizeY_mm: 1.6; SizeZ_mm: 1.35; Value2: 0.25W; SizeArea_mm2: 5.12; AEC Qualified: Y; VDC_V: 200V; AEC Category: Q200; AEC Grade: 0; SizeAreaWB_mm2: 10.92
R255 R256 = CMP-0026681-1: RES, 2.20 k, 1%, 0.1 W, 0402; Manufacturer: Panasonic; Power_W: 100mW; TempCo: 100 ppm/C; Value_Code: 2k20; U/M: EA; Value: 2.20k; Res_ohm: 2.2k; SizeX_mm: 1; SizeY_mm: 0.5; SizeZ_mm: 0.6; Value2: 0.1W; VDC_V: 50V; AEC Category: Q200
S2 = CMP-0002328-1: Switch, SPST, 0.05 A, 12 VDC, SMD; Manufacturer: Diptronics; CurrentRating_mA: 50A; PositionCount: 1; SizeX_mm: 7.8; SizeY_mm: 3.5; SizeArea_mm2: 27.3; VDC_V: 12V; SizeAreaWB_mm2: 53.9
U5 = CMP-0121877-1: SIMPLE SWITCHER® Power Converter, 4-V to 42-V, 1-A Buck Converter, SOT23; Manufacturer: Texas Instruments; SizeZ_mm: 1.45mm; AEC Qualified: No; AEC Grade: NA; Max Duty Cycle: 98%; Max Supply Voltage: 42V; Min Supply Voltage: 4V; Nominal Supply Current: 26.5-420uA; Number Of Outputs: 1; Output Type: AdjustableProgrammable; Output Voltage: 0.8-28V; Standoff Height: 0mm; Switching Frequency: 1.1MHz; TJmax_C: +150°C
U6 = CMP-0860463-2: Automotive 150-mA high-voltage ultra-low-IQ low-dropout (LDO) linear regulator, DRV0006A (WSON-6); Alternate Manufacturer: Texas Instruments; AEC Qualified: Y; SizeY_mm: 2; SizeZ_mm: 0.8; AEC Category: Q200; CompType: IC; SizeArea_mm2: 4; SizeAreaWB_mm2: 9
U7 = CMP-0098322-4: 1.5W, High-Density, >3 kVRMS Isolated DC-DC Converter; Manufacturer: Texas Instruments; SizeZ_mm: 1.05mm; AEC Qualified: No; AEC Grade: NA; Max Supply Voltage: 5.5V; Min Supply Voltage: 4.5V; Number Of Outputs: 1; Output Type: Fixed; Output Voltage: 5V; AEC Category: Q200; CompType: IC
U8 = CMP-0094881-1: General Purpose Reinforced and Basic Dual-Channel Automotive Digital Isolators with Robust EMC; Manufacturer: Texas Instruments; TaMin_C: -40°C; AEC Grade: Grade 1; Interface: LVCMOS; TJmax_C: +150°C; SizeZ_mm: 2.8mm; TaMax_C: +125°C; Max Supply Voltage: 5.5V; Min Supply Voltage: 1.71V; Standoff Height: 0.36mm; AEC Qualified: Yes
U9 U10 = CMP-0120108-2: 1.5W, High-Density, >5 kVRMS Isolated DC-DC Converter; Manufacturer: Texas Instruments; SizeZ_mm: 2.6mm; AEC Qualified: No; Max Supply Voltage: 5.5V; Min Supply Voltage: 4.5V; Number Of Outputs: 1; Output Type: AdjustableProgrammable; Output Voltage: 5/5.5V; Standoff Height: 0.14mm; AEC Category: Q200; CompType: IC
U13 = CMP-0089901-1: Automotive High Speed CAN Transceiver; Manufacturer: Texas Instruments; Min Supply Voltage: 4.5V; TaMin_C: -40°C; AEC Grade: Grade 1; Standoff Height: 0mm; SizeZ_mm: 1.1mm; TaMax_C: +125°C; Max Supply Voltage: 5.5V; Nominal Supply Current: 5-180mA; TJmax_C: +150°C; AEC Qualified: Yes
U14 = CMP-0043125-4: Low-Capacitance 6-Channel +/-15 kV ESD Protection Array for High-Speed Data Interfaces, RSE0008A (UQFN-8); Manufacturer: Texas Instruments; IO Leakage Current(nA): 1; IO Capacitance(Typ)(pF): 1.6; 1394 / Firewire: TRUE; Eco-Plan: Green (RoHS & no Sb/Br); SubFamily: ESD Solution; Breakdown Voltage(Min)(V): 6; IEC 61000-4-2 Air-Gap(+/- kV): 12; IEC 61000-4-2 Contact(+/- kV): 8; AEC Category: Q200; AEC Qualified: N; CompType: IC; SizeAreaWB_mm2: 6.25; SizeArea_mm2: 2.25; SizeX_mm: 1.5; SizeZ_mm: 0.6
U50 = ISO7831DWW: Automotive, robust EMC, quad-channel, 3/1, reinforced digital isolator 16-SOIC -40 to 125; Manufacturer_Name: Texas Instruments; Manufacturer_Part_Number: ISO7741FQDWWQ1
Y1 = CMP-2000-05089-1: Turning Fork Crystal Unit, 32.768 KHz, -40 to 85 degC, 2-Pin SMD, RoHS, Tape and Reel; Manufacturer: Citizen Micro HumanTech; Package Version: Rev. 1.4, 09/2012
Y2 = CMP-0098168-2: Crystal 40MHz ±10ppm (Tol) ±20ppm (Stability) 12pF FUND 40Ohm 4-Pin Mini-CSMD T/R; Manufacturer: Seiko Epson; SizeZ_mm: 0.6mm; AEC Qualified: No; Esr: 40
